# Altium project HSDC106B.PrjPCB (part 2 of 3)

## Sheet HSDC106B_EVM_DP83561_64p_PHY.SchDoc
size 431 x 279 mm; Date: Not shown in title block; ApprovedBy: Not shown in title block; CheckedBy: Not shown in title block; Author: Not shown in title block; CompanyName: Not shown in title block; DrawnBy: Justin Lazaruk; Engineer: Not shown in title block; Organization: Not shown in title block; Address1: Not shown in title block; Address2: Not shown in title block; Address3: Not shown in title block; Address4: Not shown in title block; DocumentNumber: 2; Revision: Use project parameter SCH_Rev; SheetNumber: 2; SheetTotal: 9; PageSetup: Record=PageOptions¦CenterHorizontal=True¦CenterVertical=True¦PrintScale=1.00¦XCorrection=1.00¦YCorrection=1.00¦PrintKind=0¦BorderSize=5000000¦LeftOffset=0¦BottomOffset=0¦Orientation=2¦PaperLength=1000¦PaperWidth=1000¦Scale=100¦PaperSource=15¦PrintQuality=600¦MediaType=1¦DitherType=10¦PaperKind=Letter¦PrintScaleMode=1
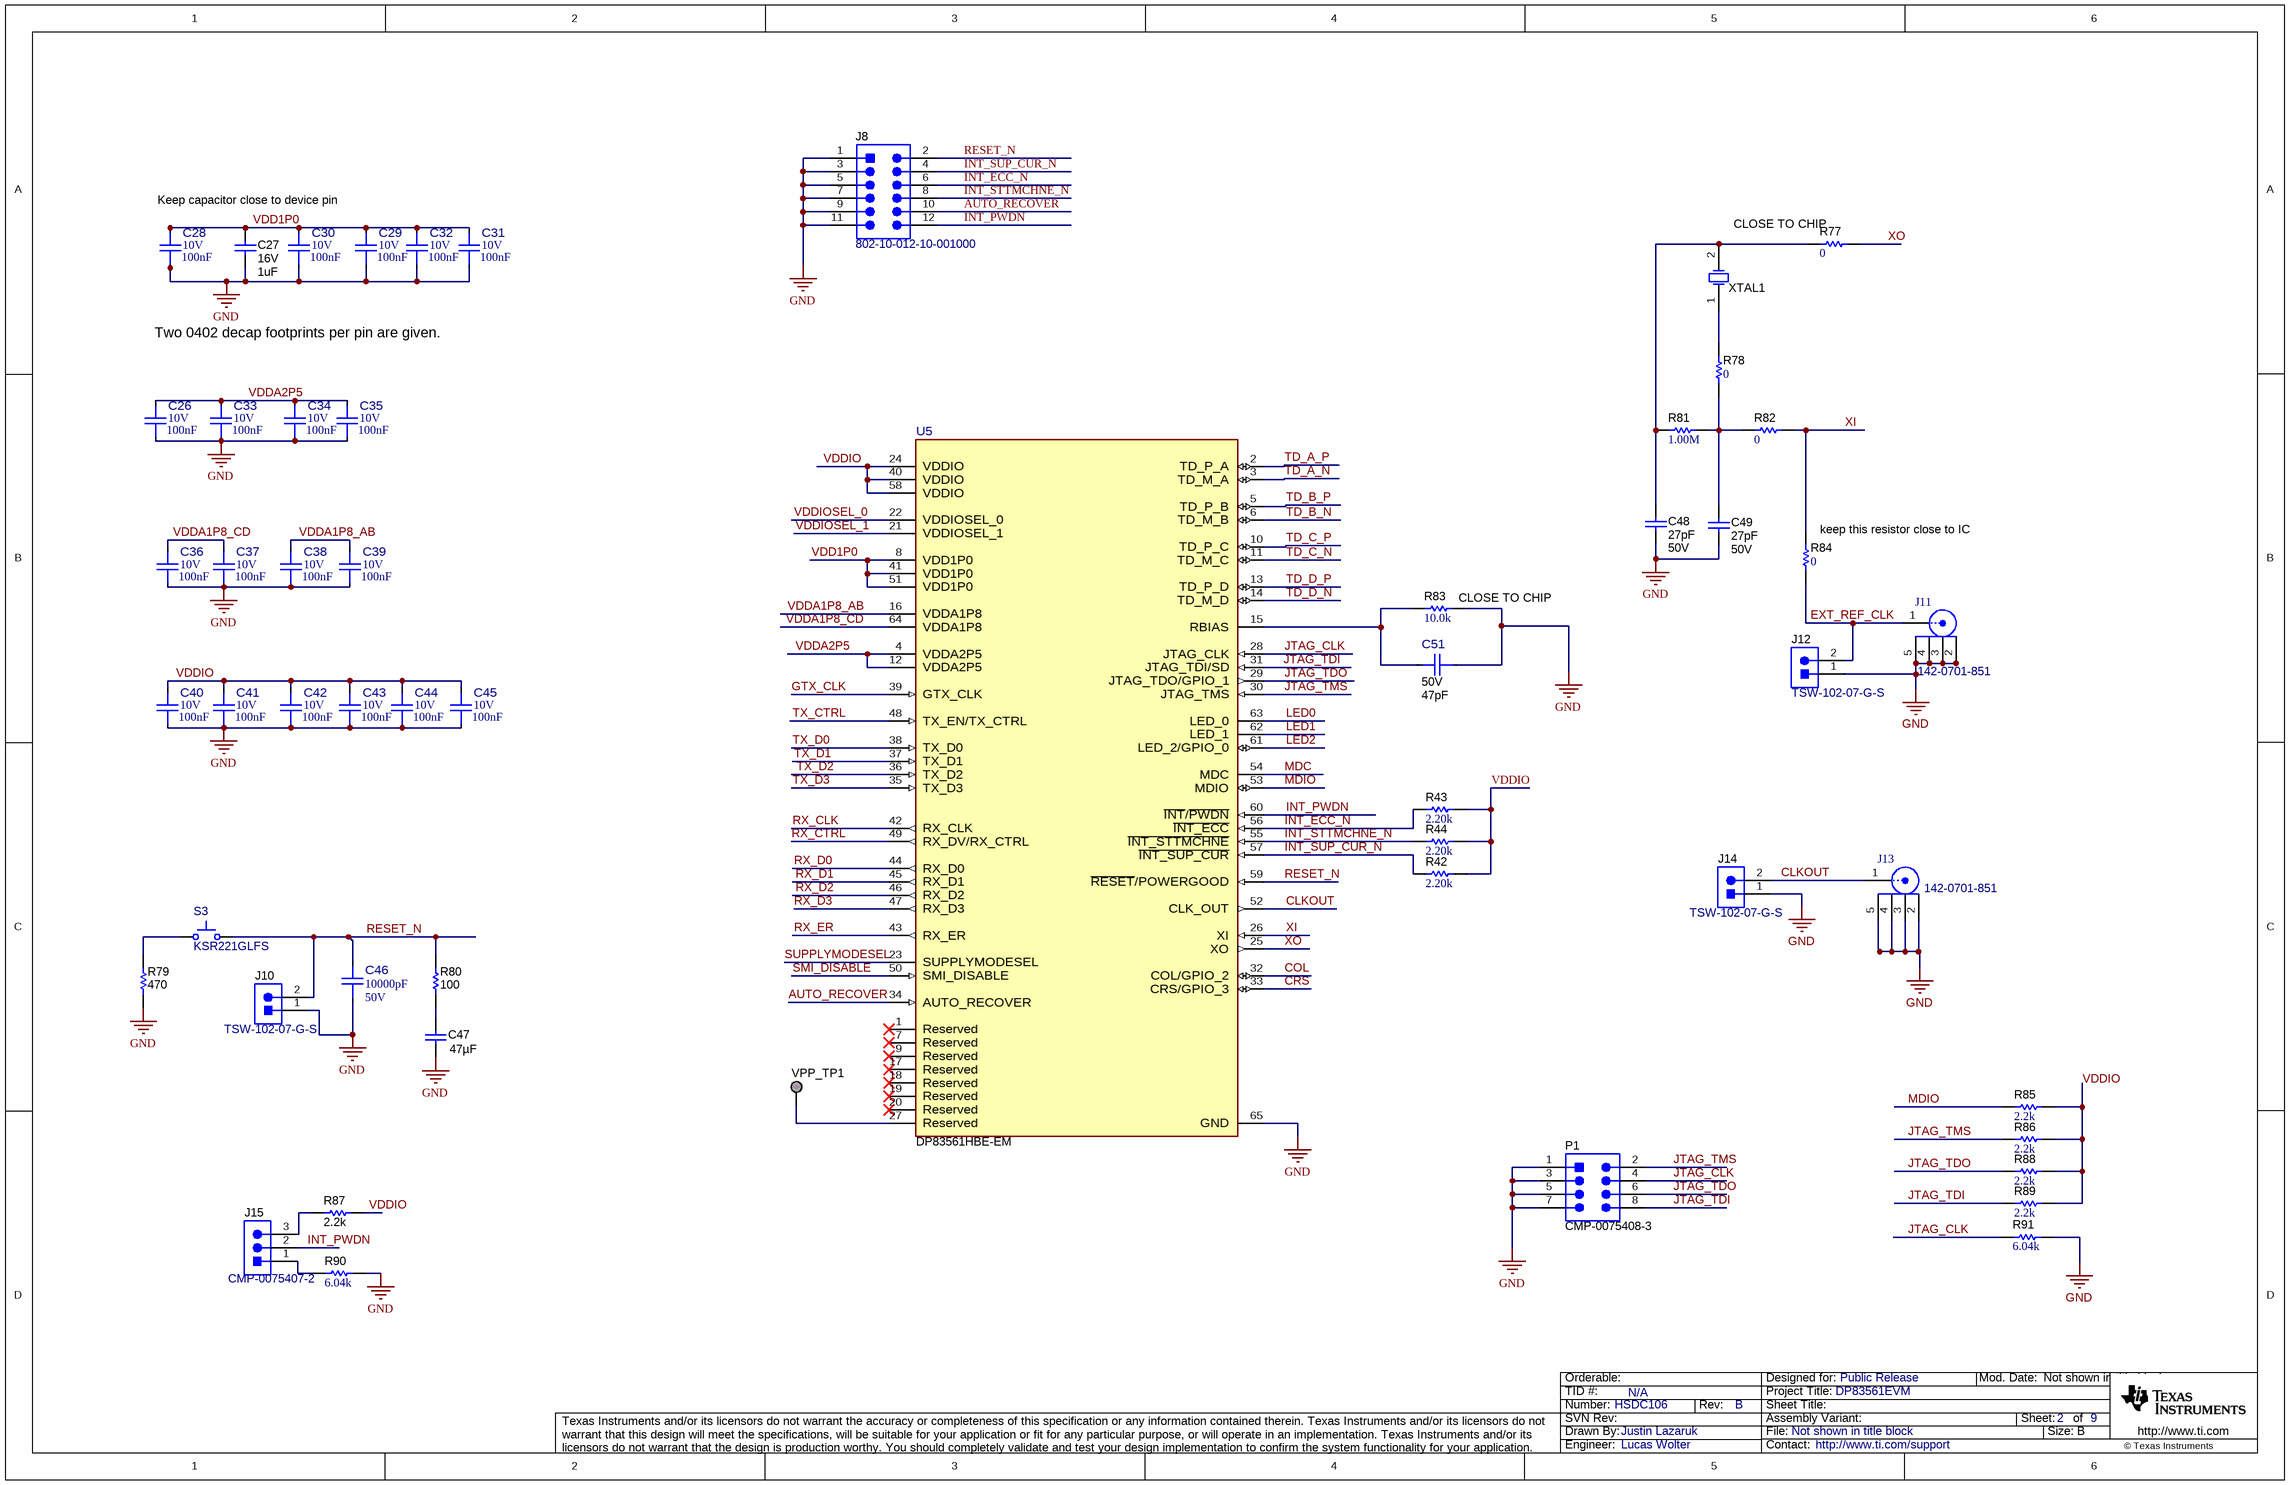
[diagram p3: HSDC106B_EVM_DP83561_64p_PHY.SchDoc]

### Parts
C26  VDC_V: 10V  ValueDisplayed: 100nF  [FP-CC0402KRX5R6BB104_0402-MFG]  (hidden comment: CC0402KRX5R6BB104)
C27  VDC_V: 16V  ValueDisplayed: 1uF  [0402]  (hidden comment: EMK105BJ105KVHF)
C28  VDC_V: 10V  ValueDisplayed: 100nF  [FP-CC0402KRX5R6BB104_0402-MFG]  (hidden comment: CC0402KRX5R6BB104)
C29  VDC_V: 10V  ValueDisplayed: 100nF  [FP-CC0402KRX5R6BB104_0402-MFG]  (hidden comment: CC0402KRX5R6BB104)
C30  VDC_V: 10V  ValueDisplayed: 100nF  [FP-CC0402KRX5R6BB104_0402-MFG]  (hidden comment: CC0402KRX5R6BB104)
C31  VDC_V: 10V  ValueDisplayed: 100nF  [FP-CC0402KRX5R6BB104_0402-MFG]  (hidden comment: CC0402KRX5R6BB104)
C32  VDC_V: 10V  ValueDisplayed: 100nF  [FP-CC0402KRX5R6BB104_0402-MFG]  (hidden comment: CC0402KRX5R6BB104)
C33  VDC_V: 10V  ValueDisplayed: 100nF  [FP-CC0402KRX5R6BB104_0402-MFG]  (hidden comment: CC0402KRX5R6BB104)
C34  VDC_V: 10V  ValueDisplayed: 100nF  [FP-CC0402KRX5R6BB104_0402-MFG]  (hidden comment: CC0402KRX5R6BB104)
C35  VDC_V: 10V  ValueDisplayed: 100nF  [FP-CC0402KRX5R6BB104_0402-MFG]  (hidden comment: CC0402KRX5R6BB104)
C36  VDC_V: 10V  ValueDisplayed: 100nF  [FP-CC0402KRX5R6BB104_0402-MFG]  (hidden comment: CC0402KRX5R6BB104)
C37  VDC_V: 10V  ValueDisplayed: 100nF  [FP-CC0402KRX5R6BB104_0402-MFG]  (hidden comment: CC0402KRX5R6BB104)
C38  VDC_V: 10V  ValueDisplayed: 100nF  [FP-CC0402KRX5R6BB104_0402-MFG]  (hidden comment: CC0402KRX5R6BB104)
C39  VDC_V: 10V  ValueDisplayed: 100nF  [FP-CC0402KRX5R6BB104_0402-MFG]  (hidden comment: CC0402KRX5R6BB104)
C40  VDC_V: 10V  ValueDisplayed: 100nF  [FP-CC0402KRX5R6BB104_0402-MFG]  (hidden comment: CC0402KRX5R6BB104)
C41  VDC_V: 10V  ValueDisplayed: 100nF  [FP-CC0402KRX5R6BB104_0402-MFG]  (hidden comment: CC0402KRX5R6BB104)
C42  VDC_V: 10V  ValueDisplayed: 100nF  [FP-CC0402KRX5R6BB104_0402-MFG]  (hidden comment: CC0402KRX5R6BB104)
C43  VDC_V: 10V  ValueDisplayed: 100nF  [FP-CC0402KRX5R6BB104_0402-MFG]  (hidden comment: CC0402KRX5R6BB104)
C44  VDC_V: 10V  ValueDisplayed: 100nF  [FP-CC0402KRX5R6BB104_0402-MFG]  (hidden comment: CC0402KRX5R6BB104)
C45  VDC_V: 10V  ValueDisplayed: 100nF  [FP-CC0402KRX5R6BB104_0402-MFG]  (hidden comment: CC0402KRX5R6BB104)
C46  ValueDisplayed: 10000pF  VDC_V: 50V  [FP-885012205067_0402-MFG]  (hidden comment: 885012205067)
C47  ValueDisplayed: 47µF  [0805_HV]  (hidden comment: GRM21BC80G476ME15L)
C48  ValueDisplayed: 27pF  VDC_V: 50V  [0603]  (hidden comment: CMP-0007116-4)
C49  ValueDisplayed: 27pF  VDC_V: 50V  [0603]  (hidden comment: CMP-0007116-4)
C51  VDC_V: 50V  ValueDisplayed: 47pF  [FP-GCM1555C1H470FA16D_0402-MFG]  (hidden comment: GCM1555C1H470FA16D)
J8  802-10-012-10-001000  [Mill-Max_802-10-012-10-001000]
J10  TSW-102-07-G-S  [TSW-102-07-G-S]
J11  142-0701-851  [Emerson_142-0701-851]
J12  TSW-102-07-G-S  [TSW-102-07-G-S]
J13  142-0701-851  [Emerson_142-0701-851]
J14  TSW-102-07-G-S  [TSW-102-07-G-S]
J15  CMP-0075407-2  [TSW-103-07-G-S]
P1  CMP-0075408-3  [TSW-104-07-G-D]
R42  ValueDisplayed: 2.20k  [0402]  (hidden comment: ERJ-2RKF2201X)
R43  ValueDisplayed: 2.20k  [0402]  (hidden comment: ERJ-2RKF2201X)
R44  ValueDisplayed: 2.20k  [0402]  (hidden comment: ERJ-2RKF2201X)
R77  ValueDisplayed: 0  [0603]  (hidden comment: CMP-0025885-5)
R78  ValueDisplayed: 0  [0603]  (hidden comment: CMP-0025885-5)
R79  ValueDisplayed: 470  [0402]  (hidden comment: CRCW0402470RJNED)
R80  ValueDisplayed: 100  [0402]  (hidden comment: ERJ-2GEJ101X)
R81  ValueDisplayed: 1.00M  [0402]  (hidden comment: CMP-0026727-1)
R82  ValueDisplayed: 0  [0603]  (hidden comment: CMP-0025885-5)
R83  ValueDisplayed: 10.0k  [0402]  (hidden comment: RMCF0402FT10K0)
R84  ValueDisplayed: 0  [0603]  (hidden comment: CMP-0025885-5)
R85  ValueDisplayed: 2.2k  [0402]  (hidden comment: CMP-0026890-5)
R86  ValueDisplayed: 2.2k  [0402]  (hidden comment: CMP-0026890-5)
R87  ValueDisplayed: 2.2k  [0402]  (hidden comment: CMP-0026890-5)
R88  ValueDisplayed: 2.2k  [0402]  (hidden comment: CMP-0026890-5)
R89  ValueDisplayed: 2.2k  [0402]  (hidden comment: CMP-0026890-5)
R90  ValueDisplayed: 6.04k  [0603]  (hidden comment: CMP-0023246-5)
R91  ValueDisplayed: 6.04k  [0603]  (hidden comment: CMP-0022558-4)
S3  KSR221GLFS  [KSR]
U5  PartNumber: DP83561HBE-EM  [HBE0064B-MFG]  (hidden comment: DP83561HBE/EM)
VPP_TP1  TP_H0.45P0.75  [TP_H045P075]  (value not drawn)  (no BOM)
XTAL1  ABM3-25.000MHZ-D2Y-T  [XTAL_ABM3]  (value not drawn)

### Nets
GND: C26.1 C27.2 C28.1 C29.1 C30.1 C31.1 C32.1 C33.1 C34.1 C35.1 C36.1 C37.1 C38.1 C39.1 C40.1 C41.1 C42.1 C43.1 C44.1 C45.1 C46.1 C47.2 C48.2 C49.2 C51.1 J8.1 J8.3 J8.5 J8.7 J8.9 J8.11 J10.1 J11.2 J11.3 J11.4 J11.5 J12.1 J13.2 J13.3 J13.4 J13.5 J14.1 P1.1 P1.3 P1.5 P1.7 R79.2 R83.2 R90.1 R91.1 U5.65(GND)
VDDIO: C40.2 C41.2 C42.2 C43.2 C44.2 C45.2 R42.2 R43.2 R44.2 R85.1 R86.1 R87.2 R88.1 R89.1 U5.24(VDDIO) U5.40(VDDIO) U5.58(VDDIO)
AUTO_RECOVER: J8.10 U5.34(AUTO_RECOVER)
CLKOUT: J13.1 J14.2 U5.52(CLK_OUT)
COL: U5.32(COL/GPIO_2)
CRS: U5.33(CRS/GPIO_3)
EXT_REF_CLK: J11.1 J12.2 R84.1
GTX_CLK: U5.39(GTX_CLK)
INT_ECC_N: J8.6 R43.1 U5.56(~{INT_ECC})
INT_PWDN: J8.12 J15.2 U5.60(~{INT}/~{PWDN})
INT_STTMCHNE_N: J8.8 R44.1 U5.55(~{INT_STTMCHNE})
INT_SUP_CUR_N: J8.4 R42.1 U5.57(~{INT_SUP_CUR})
JTAG_CLK: P1.4 R91.2 U5.28(JTAG_CLK)
JTAG_TDI: P1.8 R89.2 U5.31(JTAG_TDI/SD)
JTAG_TDO: P1.6 R88.2 U5.29(JTAG_TDO/GPIO_1)
JTAG_TMS: P1.2 R86.2 U5.30(JTAG_TMS)
LED0: U5.63(LED_0)
LED1: U5.62(LED_1)
LED2: U5.61(LED_2/GPIO_0)
MDC: U5.54(MDC)
MDIO: R85.2 U5.53(MDIO)
RESET_N: C46.2 J8.2 J10.2 R80.2 S3.2 U5.59(~{RESET}/POWERGOOD)
RX_CLK: U5.42(RX_CLK)
RX_CTRL: U5.49(RX_DV/RX_CTRL)
RX_D0: U5.44(RX_D0)
RX_D1: U5.45(RX_D1)
RX_D2: U5.46(RX_D2)
RX_D3: U5.47(RX_D3)
RX_ER: U5.43(RX_ER)
SMI_DISABLE: U5.50(SMI_DISABLE)
SUPPLYMODESEL: U5.23(SUPPLYMODESEL)
TD_A_N: U5.3(TD_M_A)
TD_A_P: U5.2(TD_P_A)
TD_B_N: U5.6(TD_M_B)
TD_B_P: U5.5(TD_P_B)
TD_C_N: U5.11(TD_M_C)
TD_C_P: U5.10(TD_P_C)
TD_D_N: U5.14(TD_M_D)
TD_D_P: U5.13(TD_P_D)
TX_CTRL: U5.48(TX_EN/TX_CTRL)
TX_D0: U5.38(TX_D0)
TX_D1: U5.37(TX_D1)
TX_D2: U5.36(TX_D2)
TX_D3: U5.35(TX_D3)
VDD1P0: C27.1 C28.2 C29.2 C30.2 C31.2 C32.2 U5.8(VDD1P0) U5.41(VDD1P0) U5.51(VDD1P0)
VDDA1P8_AB: C38.2 C39.2 U5.16(VDDA1P8)
VDDA1P8_CD: C36.2 C37.2 U5.64(VDDA1P8)
VDDA2P5: C26.2 C33.2 C34.2 C35.2 U5.4(VDDA2P5) U5.12(VDDA2P5)
VDDIOSEL_0: U5.22(VDDIOSEL_0)
VDDIOSEL_1: U5.21(VDDIOSEL_1)
XI: R82.2 R84.2 U5.26(XI)
XO: R77.2 U5.25(XO)
NetC47_1: C47.1 R80.1
NetC48_1: C48.1 R77.1 R81.1 XTAL1.2(OSC2)
NetC49_1: C49.1 R78.1 R81.2 R82.1
NetC51_2: C51.2 R83.1 U5.15(RBIAS)
NetJ15_1: J15.1 R90.2
NetJ15_3: J15.3 R87.1
NetR78_2: R78.2 XTAL1.1(OSC1)
NetR79_1: R79.1 S3.1
NetU5_27: U5.27(Reserved) VPP_TP1.1

Not connected (* = marked no-connect by the designer): U5 1(Reserved)* 7(Reserved)* 9(Reserved)* 17(Reserved)* 18(Reserved)* 19(Reserved)* 20(Reserved)*

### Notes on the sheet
- Keep capacitor close to device pin
- (near R77) CLOSE TO CHIP
- Two 0402 decap footprints per pin are given.
- (near R84) keep this resistor close to IC
- (near R83) CLOSE TO CHIP

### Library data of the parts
C26 C28-C45 = CMP-0093115-1: 0402 0.1 uF 10 V ±10 % Tolerance X5R SMT Multilayer Ceramic Capacitor; Manufacturer: YAGEO; SizeZ_mm: 0.55mm; AEC Qualified: No; AEC Grade: NA; Value: 100nF; TempCo: 30ppm/°C; Tolerance_%: 10%
C27 = CMP-0006347-2: CAP, CERM, 1 uF, 16 V, +/- 10%, X5R, 0402; Manufacturer: Taiyo Yuden; TaMin_C: -55°C; Polarized: N; SizeAreaWB_mm2: 3; Value1: Unknown; U/M: EA; Value: 1uF; TaMax_C: 85°C; SizeZ_mm: 0.6; SizeX_mm: 1; SizeY_mm: 0.5; Cap_F: 1µF; AEC Category: Q200
C46 = CMP-0090364-1: 10000pF ±10% 50V Ceramic Capacitor X7R 0402 (1005 Metric); Manufacturer: Wurth Electronics; Cap_F: 10nF; Value: 10nF; TempCo: 15%; SizeZ_mm: 0.55mm; AEC Qualified: No
C47 = CMP-0079541-1: CAP, CERM, 47 µF, 4 V,+/- 20%, X6S, 0805; Manufacturer: MuRata; SizeAreaWB_mm2: 6.75; SizeArea_mm2: 2.5; AEC Qualified: N; AEC Category: Q200; Value: 47uF; TaMax_C: 105°C; SizeZ_mm: 1.45; TaMin_C: -55°C; VDC_V: 4V; SizeY_mm: 1.25; U/M: EA; CompType: Capacitor; SizeX_mm: 2; Cap_Case: 0805
C48 C49 = CMP-0007116-4: CAP, CERM, 27 pF, 50 V, +/- 1%, C0G/NP0, 0603; PartNumber: CL10C270FB8NNNC; Manufacturer: Samsung Electro-Mechanics; Polarized: N; Value: 27pF; U/M: EA; Value1: Unknown; TaMin_C: -55°C; TaMax_C: 125°C; SizeAreaWB_mm2: 4.68; SizeZ_mm: 1; SizeX_mm: 1.6; SizeY_mm: 0.8; SizeArea_mm2: 1.28; AEC Category: Q200
C51 = CMP-0091135-2: Ceramic Capacitor for Automotive 47pF ±1% 50VDC C0G 0402 Paper T/R; Manufacturer: Murata; TempCo: 30ppm/°C; AEC Qualified: Yes; SizeZ_mm: 0.55mm; AEC Grade: Grade 1
J8 = CMP-0055098-2: Header, 2.54 mm, 6x2, Gold, TH; Manufacturer: Mill-Max; Shrouded: N; Gender: Male; Row_Count: 2; RowSpacing_mm: 2.54
J10 J12 J14 = CMP-0075405-3: Header, 100mil, 2x1, Gold, TH; Manufacturer: Samtec; Pitch_mm: 2.54; Gender: Male; Shrouded: N; Row_Count: 1; Current_A: 6.3A; Voltage_V: 550V; Cert_CSA: Y; Green_REACh: Passed; Green_Lifecycle: Active
J11 J13 = CMP-0055822-3: Connector, End launch SMA, 50 ohm, SMT; Manufacturer: Cinch Connectivity; Green_Lifecycle: Not Set; Green_REACh: Incomplete
J15 = CMP-0075407-2: Header, 100mil, 3x1, Gold, TH; Manufacturer: Samtec; Pitch_mm: 2.54; Gender: Male; Shrouded: N; Row_Count: 1; Current_A: 6.3A; Voltage_V: 550V; Cert_CSA: Y; Green_REACh: Passed; Green_Lifecycle: Active
P1 = CMP-0075408-3: Header, 100mil, 4x2, Gold, TH; Manufacturer: Samtec; Gender: Male; Row_Count: 2; Cert_CSA: Y; Pitch_mm: 2.54; Green_REACh: Passed; Voltage_V: 550V; Current_A: 6.3A; Green_Lifecycle: Active; Cert_CULUS: N
R42-R44 = CMP-0026681-1: RES, 2.20 k, 1%, 0.1 W, 0402; Manufacturer: Panasonic; Power_W: 100mW; TempCo: 100 ppm/C; Value_Code: 2k20; U/M: EA; Value: 2.20k; Res_ohm: 2.2k; SizeX_mm: 1; SizeY_mm: 0.5; SizeZ_mm: 0.6; Value2: 0.1W; VDC_V: 50V; AEC Category: Q200
R77 R78 R82 R84 = CMP-0025885-5: RES, 0, 5%, 0.1 W, 0603; PartNumber: RC0603JR-070RL; Manufacturer: Yageo; Value: 0; Value_Code: 0000; Power_W: 100mW; Value2: 0.1W; VDC_V: 75V; TempCo: 200 ppm/C; EIA_Code: E24; SizeX_mm: 1.6; SizeZ_mm: 1; SizeArea_mm2: 1.28; AEC Qualified: N; AEC Category: Q200; SizeY_mm: 0.8; SizeAreaWB_mm2: 4.68
R79 = CMP-0026934-3: RES, 470, 5%, 0.063 W, AEC-Q200 Grade 0, 0402; Manufacturer: Vishay-Dale; Value: 470; Value_Code: 470R; Power_W: 63mW; Value2: 0.063W; VDC_V: 50V; TempCo: 200 ppm/C; EIA_Code: E24; AEC Category: Q200; AEC Grade: 0; AEC Qualified: Y; SizeArea_mm2: 0.5; SizeX_mm: 1; SizeZ_mm: 0.6
R80 = CMP-0026993-2: RES, 100, 5%, 0.1 W, AEC-Q200 Grade 0, 0402; Manufacturer: Panasonic; Power_W: 100mW; TempCo: 200 ppm/C; Value_Code: 100R; U/M: EA; Value: 100; EIA_Code: E24; SizeX_mm: 1; SizeY_mm: 0.5; SizeZ_mm: 0.6; Value2: 0.1W; AEC Qualified: Y; AEC Grade: 0; AEC Category: Q200
R81 = CMP-0026727-1: RES, 1.00 M, 1%, 0.063 W, 0402; PartNumber: RC0402FR-071ML; Manufacturer: Yageo America; Value: 1.00Meg; Res_ohm: 1M; Value_Code: 1M00; Power_W: 63mW; Value2: 0.063W; TempCo: 100 ppm/C; EIA_Code: E96; U/M: EA; SizeX_mm: 1; SizeY_mm: 0.5; SizeZ_mm: 0.6; AEC Category: Q200
R83 = CMP-0026754-1: RES, 10.0 k, 1%, 0.063 W, AEC-Q200 Grade 0, 0402; Manufacturer: Stackpole Electronics Inc; Power_W: 63mW; TempCo: 100 ppm/C; Value_Code: 10k0; U/M: EA; Value: 10.0k; EIA_Code: E96; Res_ohm: 10k; SizeX_mm: 1; SizeY_mm: 0.5; SizeZ_mm: 0.6; Value2: 0.063W; AEC Qualified: Y; VDC_V: 50V; AEC Grade: 0; AEC Category: Q200
R85-R89 = CMP-0026890-5: RES, 2.2 k, 5%, 0.063 W, AEC-Q200 Grade 0, 0402; PartNumber: CRCW04022K20JNED; Manufacturer: Vishay-Dale; Value: 2.2k; Value_Code: 2k20; Power_W: 63mW; Value2: 0.063W; VDC_V: 50V; TempCo: 200 ppm/C; EIA_Code: E24; SizeX_mm: 1; SizeY_mm: 0.5; SizeZ_mm: 0.6; AEC Qualified: Y; AEC Category: Q200; AEC Grade: 0
R90 = CMP-0023246-5: RES, 6.04 k, 1%, 0.1 W, 0603; PartNumber: RC0603FR-076K04L; Manufacturer: Yageo; Value: 6.04k; Value_Code: 6k04; Power_W: 100mW; Value2: 0.1W; VDC_V: 75V; TempCo: 100 ppm/C; EIA_Code: E96; SizeX_mm: 1.6; SizeY_mm: 0.8; SizeZ_mm: 1; SizeArea_mm2: 1.28; AEC Qualified: N; AEC Category: Q200; SizeAreaWB_mm2: 4.68
R91 = CMP-0022558-4: RES, 6.04 k, 1%, 0.1 W, AEC-Q200 Grade 0, 0603; PartNumber: CRCW06036K04FKEA; Manufacturer: Vishay-Dale; Value: 6.04k; Value_Code: 6k04; Power_W: 100mW; Value2: 0.1W; VDC_V: 75V; TempCo: 100 ppm/C; EIA_Code: E96; SizeX_mm: 1.6; SizeY_mm: 0.8; SizeZ_mm: 1; SizeArea_mm2: 1.28; AEC Qualified: Y; AEC Category: Q200; AEC Grade: 0
S3 = CMP-0002170-2: Switch, Normally open, 2.3N force, 200k operations, SMD; Manufacturer: C&K Components; CurrentRating_mA: 1.001kA; SwitchFunction: Off-Mom; Circuit: SPST Switch; VDC_V: 32V; PositionCount: 1
U5 = CMP-0090870-2: Hi-Reliability, High Immunity, Radiation Resistant, Gigabit Ethernet PHY; Manufacturer: Texas Instruments; Data Rate: 1000Mbits/s; Simplex Duplex: Full-Duplex; Min Supply Voltage: 1.045V; Max Supply Voltage: 3.45V; Interface: Ethernet,Other; Number Of Channels: 1; SizeZ_mm: 3.53mm; AEC Qualified: No; AEC Category: Q200; CompType: IC
VPP_TP1 = CMP-0003719-1: Testpoint; Manufacturer: Texas Instruments; CompType: Pad
XTAL1 = CMP-0004620-3: Crystal, 25 MHz, 18 pF, SMD; Manufacturer: Abracon Corporation; TaMin_C: -40°C; Frequency Stability: +/-30ppm; Frequency_Fixed: 25MHz; TaMax_C: 85°C

## Sheet HSDC106B_EVM_DP83561_64p_MSP430.SchDoc
size 431 x 279 mm; Date: Not shown in title block; ApprovedBy: Not shown in title block; CheckedBy: Not shown in title block; Author: Not shown in title block; CompanyName: Not shown in title block; DrawnBy: Justin Lazaruk; Engineer: Not shown in title block; Organization: Not shown in title block; Address1: Not shown in title block; Address2: Not shown in title block; Address3: Not shown in title block; Address4: Not shown in title block; DocumentNumber: 7; Revision: Use project parameter SCH_Rev; SheetNumber: 7; SheetTotal: 9; PageSetup: Record=PageOptions¦CenterHorizontal=True¦CenterVertical=True¦PrintScale=1.00¦XCorrection=1.00¦YCorrection=1.00¦PrintKind=0¦BorderSize=5000000¦LeftOffset=0¦BottomOffset=0¦Orientation=2¦PaperLength=1000¦PaperWidth=1000¦Scale=100¦PaperSource=15¦PrintQuality=600¦MediaType=1¦DitherType=10¦PaperKind=Letter¦PrintScaleMode=1
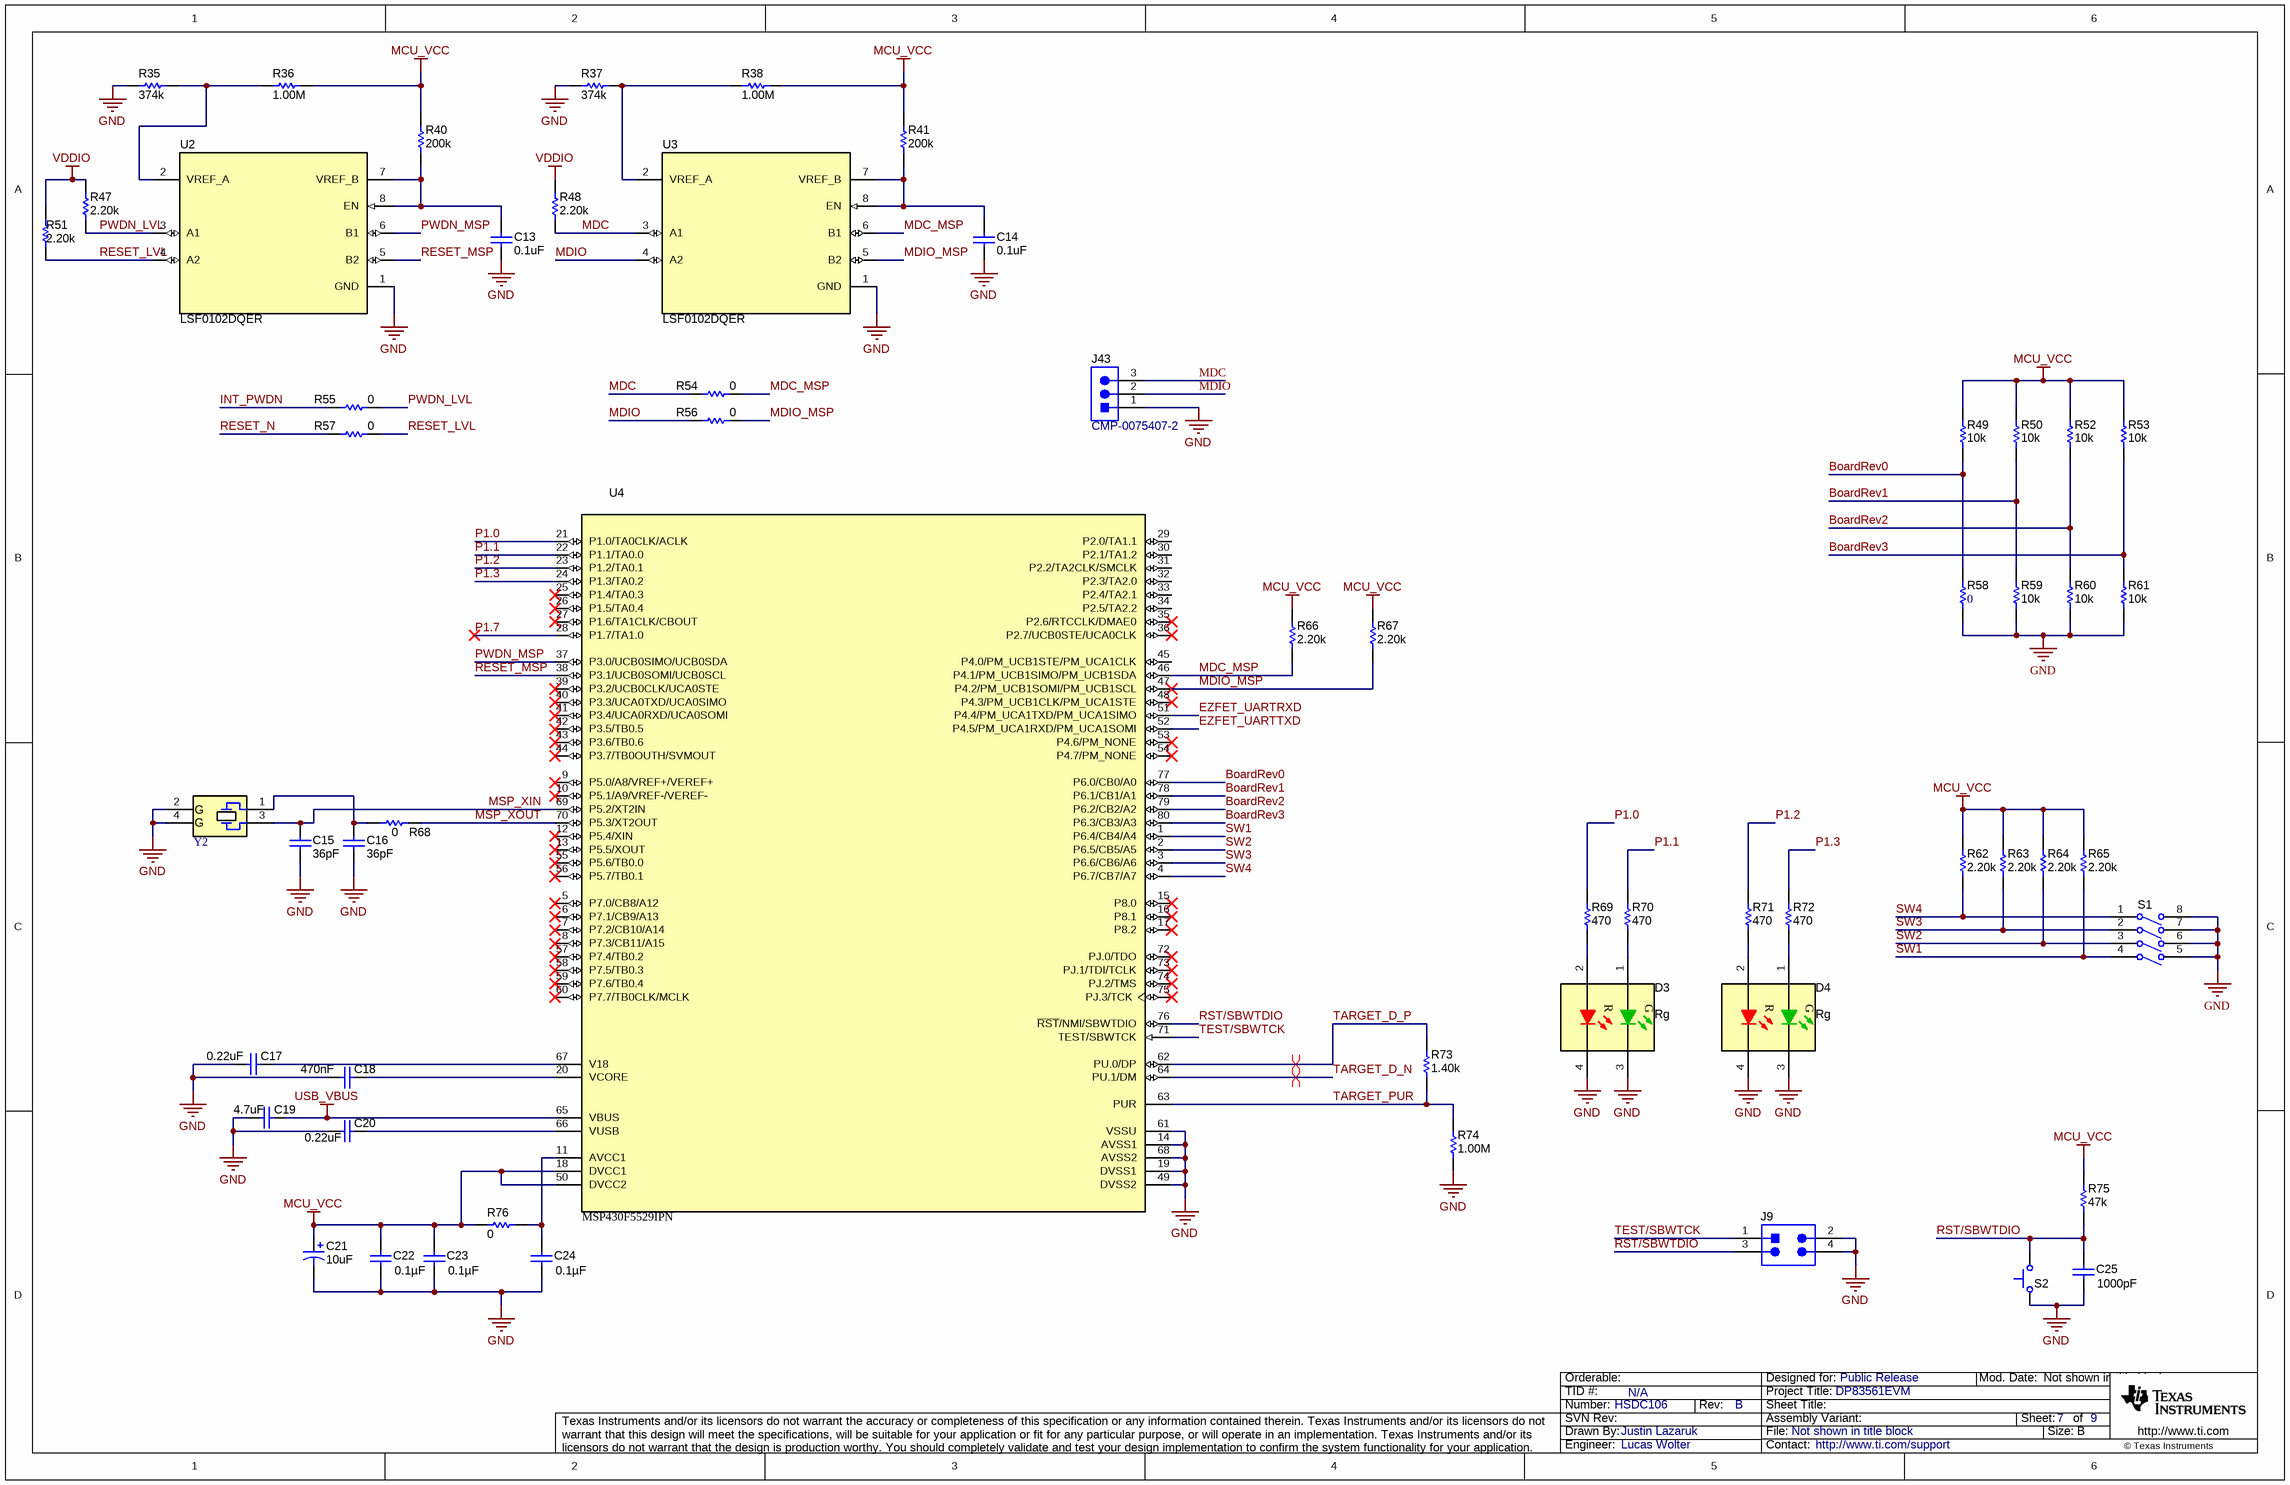
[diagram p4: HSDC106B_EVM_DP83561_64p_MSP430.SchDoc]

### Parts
C13  ValueDisplayed: 0.1uF  [0402]  (hidden comment: GCM155R71H104KE02D)
C14  ValueDisplayed: 0.1uF  [0402]  (hidden comment: GCM155R71H104KE02D)
C15  ValueDisplayed: 36pF  [0402]  (hidden comment: CL05C360JB5NNNC)
C16  ValueDisplayed: 36pF  [0402]  (hidden comment: CL05C360JB5NNNC)
C17  ValueDisplayed: 0.22uF  [0603]  (hidden comment: C0603C224Z4VACTU)
C18  Cap_F: 470nF  [0603]  (hidden comment: GCM188R71C474KA55D)
C19  ValueDisplayed: 4.7uF  [0603]  (hidden comment: C1608X5R1V475K080AC)
C20  ValueDisplayed: 0.22uF  [0603]  (hidden comment: C0603C224Z4VACTU)
C21  ValueDisplayed: 10uF  [7343-31]  (hidden comment: TPSD106K035R0125)
C22  ValueDisplayed: 0.1µF  [0402]  (hidden comment: C0402C104K8RACTU)
C23  ValueDisplayed: 0.1µF  [0402]  (hidden comment: C0402C104K8RACTU)
C24  ValueDisplayed: 0.1µF  [0402]  (hidden comment: C0402C104K8RACTU)
C25  ValueDisplayed: 1000pF  [0402]  (hidden comment: GRM1555C1H102JA01D)
D3  value Rg  [HSMF-C165_RG]  (hidden comment: HSMF-C165)
D4  value Rg  [HSMF-C165_RG]  (hidden comment: HSMF-C165)
J9  TSW-102-07-G-D  [TSW-102-07-G-D]  (value not drawn)
J43  CMP-0075407-2  [TSW-103-07-G-S]
R35  ValueDisplayed: 374k  [0402]  (hidden comment: CRCW0402374KFKED)
R36  ValueDisplayed: 1.00M  [0402]  (hidden comment: ERJ-2RKF1004X)
R37  ValueDisplayed: 374k  [0402]  (hidden comment: CRCW0402374KFKED)
R38  ValueDisplayed: 1.00M  [0402]  (hidden comment: ERJ-2RKF1004X)
R40  ValueDisplayed: 200k  [0603]  (hidden comment: CRCW0603200KJNEA)
R41  ValueDisplayed: 200k  [0603]  (hidden comment: CRCW0603200KJNEA)
R47  ValueDisplayed: 2.20k  [0402]  (hidden comment: CRCW04022K20FKED)
R48  ValueDisplayed: 2.20k  [0402]  (hidden comment: CRCW04022K20FKED)
R49  ValueDisplayed: 10k  [0402]  (hidden comment: CRCW040210K0JNED)
R50  ValueDisplayed: 10k  [0402]  (hidden comment: CRCW040210K0JNED)
R51  ValueDisplayed: 2.20k  [0402]  (hidden comment: CRCW04022K20FKED)
R52  ValueDisplayed: 10k  [0402]  (hidden comment: CRCW040210K0JNED)
R53  ValueDisplayed: 10k  [0402]  (hidden comment: CRCW040210K0JNED)
R54  ValueDisplayed: 0  [0402]  (hidden comment: ERJ-2GE0R00X)
R55  ValueDisplayed: 0  [0402]  (hidden comment: ERJ-2GE0R00X)
R56  ValueDisplayed: 0  [0402]  (hidden comment: ERJ-2GE0R00X)
R57  ValueDisplayed: 0  [0402]  (hidden comment: ERJ-2GE0R00X)
R58  ValueDisplayed: 0  [0402]  (hidden comment: ERJ-2GE0R00X)
R59  ValueDisplayed: 10k  [0402]  (hidden comment: CRCW040210K0JNED)
R60  ValueDisplayed: 10k  [0402]  (hidden comment: CRCW040210K0JNED)
R61  ValueDisplayed: 10k  [0402]  (hidden comment: CRCW040210K0JNED)
R62  ValueDisplayed: 2.20k  [0402]  (hidden comment: CRCW04022K20FKED)
R63  ValueDisplayed: 2.20k  [0402]  (hidden comment: CRCW04022K20FKED)
R64  ValueDisplayed: 2.20k  [0402]  (hidden comment: CRCW04022K20FKED)
R65  ValueDisplayed: 2.20k  [0402]  (hidden comment: CRCW04022K20FKED)
R66  ValueDisplayed: 2.20k  [0402]  (hidden comment: CRCW04022K20FKED)
R67  ValueDisplayed: 2.20k  [0402]  (hidden comment: CRCW04022K20FKED)
R68  ValueDisplayed: 0  [0402]  (hidden comment: CRCW04020000Z0ED)
R69  ValueDisplayed: 470  [0201]  (hidden comment: RC0201JR-07470RL)
R70  ValueDisplayed: 470  [0201]  (hidden comment: RC0201JR-07470RL)
R71  ValueDisplayed: 470  [0201]  (hidden comment: RC0201JR-07470RL)
R72  ValueDisplayed: 470  [0201]  (hidden comment: RC0201JR-07470RL)
R73  ValueDisplayed: 1.40k  [0402]  (hidden comment: CRCW04021K40FKED)
R74  ValueDisplayed: 1.00M  [0402]  (hidden comment: CRCW04021M00FKED)
R75  ValueDisplayed: 47k  [0402]  (hidden comment: CRCW040247K0JNED)
R76  ValueDisplayed: 0  [0402]  (hidden comment: CRCW04020000Z0ED)
S1  218-4LPST  [SW_218-4LPST]  (value not drawn)
S2  KSR221GLFS  [KSR]  (value not drawn)
U2  LSF0102DQER  [DQE0008A]
U3  LSF0102DQER  [DQE0008A]
U4  MSP430F5529IPN  [PN0080A_N]
Y2  ECS-240-20-33-DU-TR  [ECS_ECX-32]  (value not drawn)

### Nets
GND: C13.2 C14.2 C15.2 C16.2 C17.2 C18.2 C19.1 C20.2 C21.2(-) C22.2 C23.2 C24.2 C25.2 D3.3(K) D3.4(K) D4.3(K) D4.4(K) J9.2 J9.4 J43.1 R35.1 R37.1 R58.1 R59.1 R60.1 R61.1 R74.2 S1.5(B4) S1.6(B3) S1.7(B2) S1.8(B1) S2.1 U2.1(GND) U3.1(GND) U4.14(AVSS1) U4.19(DVSS1) U4.49(DVSS2) U4.61(VSSU) U4.68(AVSS2) Y2.2(GND) Y2.4(GND)
MCU_VCC: C21.1(+) C22.1 C23.1 R36.2 R38.2 R40.2 R41.2 R49.2 R50.2 R52.2 R53.2 R62.2 R63.2 R64.2 R65.2 R66.2 R67.2 R75.1 R76.1 U4.18(DVCC1) U4.50(DVCC2)
USB_VBUS: C19.2 U4.65(VBUS)
VDDIO: R47.2 R48.2 R51.2
BoardRev0: R49.1 R58.2 U4.77(P6.0/CB0/A0)
BoardRev1: R50.1 R59.2 U4.78(P6.1/CB1/A1)
BoardRev2: R52.1 R60.2 U4.79(P6.2/CB2/A2)
BoardRev3: R53.1 R61.2 U4.80(P6.3/CB3/A3)
EZFET_UARTRXD: U4.51(P4.4/PM_UCA1TXD/PM_UCA1SIMO)
EZFET_UARTTXD: U4.52(P4.5/PM_UCA1RXD/PM_UCA1SOMI)
INT_PWDN: R55.1
MDC: J43.3 R48.1 R54.1 U3.3(A1)
MDC_MSP: R54.2 R66.1 U3.6(B1) U4.46(P4.1/PM_UCB1SIMO/PM_UCB1SDA)
MDIO: J43.2 R56.1 U3.4(A2)
MDIO_MSP: R56.2 R67.1 U3.5(B2) U4.47(P4.2/PM_UCB1SOMI/PM_UCB1SCL)
MSP_XIN: C15.1 U4.69(P5.2/XT2IN) Y2.3
MSP_XOUT: R68.2 U4.70(P5.3/XT2OUT)
P1.0: R69.2 U4.21(P1.0/TA0CLK/ACLK)
P1.1: R70.2 U4.22(P1.1/TA0.0)
P1.2: R71.2 U4.23(P1.2/TA0.1)
P1.3: R72.2 U4.24(P1.3/TA0.2)
P1.7: U4.28(P1.7/TA1.0)
PWDN_LVL: R47.1 R55.2 U2.3(A1)
PWDN_MSP: U2.6(B1) U4.37(P3.0/UCB0SIMO/UCB0SDA)
RESET_LVL: R51.1 R57.2 U2.4(A2)
RESET_MSP: U2.5(B2) U4.38(P3.1/UCB0SOMI/UCB0SCL)
RESET_N: R57.1
RST/SBWTDIO: C25.1 J9.3 R75.2 S2.2 U4.76(~{RST}/NMI/SBWTDIO)
SW1: R65.1 S1.4(A4) U4.1(P6.4/CB4/A4)
SW2: R64.1 S1.3(A3) U4.2(P6.5/CB5/A5)
SW3: R63.1 S1.2(A2) U4.3(P6.6/CB6/A6)
SW4: R62.1 S1.1(A1) U4.4(P6.7/CB7/A7)
TARGET_D_N: U4.64(PU.1/DM)
TARGET_D_P: R73.2 U4.62(PU.0/DP)
TARGET_PUR: R73.1 R74.1 U4.63(PUR)
TEST/SBWTCK: J9.1 U4.71(TEST/SBWTCK)
NetC13_1: C13.1 R40.1 U2.7(VREF_B) U2.8(EN)
NetC14_1: C14.1 R41.1 U3.7(VREF_B) U3.8(EN)
NetC16_1: C16.1 R68.1 Y2.1
NetC17_1: C17.1 U4.67(V18)
NetC18_1: C18.1 U4.20(VCORE)
NetC20_1: C20.1 U4.66(VUSB)
NetC24_1: C24.1 R76.2 U4.11(AVCC1)
NetD3_1: D3.1(A) R70.1
NetD3_2: D3.2(A) R69.1
NetD4_1: D4.1(A) R72.1
NetD4_2: D4.2(A) R71.1
NetR35_2: R35.2 R36.1 U2.2(VREF_A)
NetR37_2: R37.2 R38.1 U3.2(VREF_A)

Not connected (* = marked no-connect by the designer): U4 5(P7.0/CB8/A12)* 6(P7.1/CB9/A13)* 7(P7.2/CB10/A14)* 8(P7.3/CB11/A15)* 9(P5.0/A8/VREF+/VEREF+)* 10(P5.1/A9/VREF-/VEREF-)* 12(P5.4/XIN)* 13(P5.5/XOUT)* 15(P8.0)* 16(P8.1)* 17(P8.2)* 25(P1.4/TA0.3)* 26(P1.5/TA0.4)* 27(P1.6/TA1CLK/CBOUT)* 29(P2.0/TA1.1) 30(P2.1/TA1.2) 31(P2.2/TA2CLK/SMCLK) 32(P2.3/TA2.0) 33(P2.4/TA2.1) 34(P2.5/TA2.2) 35(P2.6/RTCCLK/DMAE0)* 36(P2.7/UCB0STE/UCA0CLK)* 39(P3.2/UCB0CLK/UCA0STE)* 40(P3.3/UCA0TXD/UCA0SIMO)* 41(P3.4/UCA0RXD/UCA0SOMI)* 42(P3.5/TB0.5)* 43(P3.6/TB0.6)* 44(P3.7/TB0OUTH/SVMOUT)* 45(P4.0/PM_UCB1STE/PM_UCA1CLK) 48(P4.3/PM_UCB1CLK/PM_UCA1STE)* 53(P4.6/PM_NONE)* 54(P4.7/PM_NONE)* 55(P5.6/TB0.0)* 56(P5.7/TB0.1)* 57(P7.4/TB0.2)* 58(P7.5/TB0.3)* 59(P7.6/TB0.4)* 60(P7.7/TB0CLK/MCLK)* 72(PJ.0/TDO)* 73(PJ.1/TDI/TCLK)* 74(PJ.2/TMS)* 75(PJ.3/TCK)*

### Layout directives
differential pair: TARGET_D_N, TARGET_D_P

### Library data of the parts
C13 C14 = CMP-0006356-2: CAP, CERM, 0.1 uF, 50 V, +/- 10%, X7R, AEC-Q200 Grade 1, 0402; Manufacturer: MuRata; TaMin_C: -55°C; Polarized: N; SizeAreaWB_mm2: 3; Value1: Unknown; U/M: EA; Value: 0.1uF; TaMax_C: 125°C; SizeZ_mm: 0.6; SizeX_mm: 1; SizeY_mm: 0.5; Value2: 50V; AEC Qualified: Y; Cap_F: 100nF; AEC Category: Q200
C15 C16 = CMP-0083839-1: CAP, CERM, 36 pF, 50 V,+/- 5%, C0G/NP0, 0402; Manufacturer: Samsung Electro-Mechanics; SizeAreaWB_mm2: 3; SizeArea_mm2: 0.5; AEC Qualified: N; AEC Category: Q200; Value: 36pF; TaMax_C: 125°C; SizeZ_mm: 0.6; TaMin_C: -55°C; VDC_V: 50V; U/M: EA; SizeX_mm: 1
C17 C20 = CMP-0006905-4: CAP, CERM, 0.22 uF, 16 V, +80/-20%, Y5V, 0603; Manufacturer: Kemet; TaMin_C: -30°C; Polarized: N; SizeAreaWB_mm2: 4.68; Value1: Unknown; U/M: EA; Value: 0.22uF; TaMax_C: 85°C; Tolerance_%: 80%; SizeZ_mm: 1; SizeX_mm: 1.6; SizeY_mm: 0.8; Value2: 16V; SizeArea_mm2: 1.28; Cap_F: 220nF; AEC Category: Q200
C18 = CMP-0007138-4: CAP, CERM, 0.47 uF, 16 V, +/- 10%, X7R, AEC-Q200 Grade 1, 0603; Manufacturer: MuRata; TaMin_C: -55°C; Polarized: N; SizeAreaWB_mm2: 4.68; Value1: Unknown; U/M: EA; Value: 0.47uF; TaMax_C: 125°C; SizeZ_mm: 1; SizeX_mm: 1.6; SizeY_mm: 0.8; Value2: 16V; SizeArea_mm2: 1.28; AEC Qualified: Y; AEC Category: Q200
C19 = CMP-0007022-5: CAP, CERM, 4.7 uF, 35 V, +/- 10%, X5R, 0603; Manufacturer: TDK; Polarized: N; CompType: Capacitor; Value: 4.7uF; U/M: EA; Cap_F: 4.7µF; ESR_ohm: 3.728m; Value1: 0.003728 ohm; VDC_V: 35V; IRMS_A: 2.69359A; TaMin_C: -55°C; TaMax_C: 85°C; SizeArea_mm2: 1.28; SizeAreaWB_mm2: 4.68; SizeX_mm: 1.6; SizeY_mm: 0.8; SizeZ_mm: 1; AEC Category: Q200
C21 = CMP-0011855-2: CAP, TA, 10 uF, 35 V, +/- 10%, 0.125 ohm, SMD; Manufacturer: AVX; Polarized: Y; CompType: Capacitor; Value: 10uF; U/M: EA; Cap_F: 10µF; VDC_V: 35V; ESR_ohm: 1.25d; IRMS_A: 9.86dA; TaMin_C: -55°C; TaMax_C: 125°C; Cap_Case: D; AEC Category: Q200; SizeArea_mm2: 31.39; SizeAreaWB_mm2: 58.59; SizeX_mm: 7.3; SizeY_mm: 4.3; SizeZ_mm: 3.1
C22-C24 = CMP-0078241-1: CAP, CERM, 0.1 µF, 10 V,+/- 10%, X7R, 0402; Manufacturer: Kemet; TaMin_C: -55°C; Polarized: N; SizeAreaWB_mm2: 3; U/M: EA; Value: 0.1uF; TaMax_C: 125°C; SizeZ_mm: 0.6; SizeX_mm: 1; SizeY_mm: 0.5; Value2: 10V; Cap_F: 100nF; AEC Category: Q200
C25 = CMP-0006412-2: CAP, CERM, 1000 pF, 50 V, +/- 5%, C0G/NP0, 0402; Manufacturer: MuRata; TaMin_C: -55°C; Polarized: N; SizeAreaWB_mm2: 3; Value1: Unknown; U/M: EA; Value: 1000pF; TaMax_C: 125°C; SizeZ_mm: 0.6; SizeX_mm: 1; SizeY_mm: 0.5; Value2: 50V; Cap_F: 1nF; AEC Category: Q200
D3 D4 = CMP-0002934-2: LED, Rg, SMD; Manufacturer: Avago; Vf_V: 2.2V; Io_A: 20mA; Vr_V: 5V; Ir_A: 100µA; Tjmax_C: 85°C; Value1: W; LuminousIntensity_IV: 20; Angle: 120; U/M: EA
J9 = CMP-0075404-1: Header, 100mil, 2x2, Gold, TH; Manufacturer: Samtec; Pitch_mm: 2.54; Gender: Male; Shrouded: N; Row_Count: 2; Current_A: 6.3A; Voltage_V: 550V; Cert_CSA: Y; CNHeader: True; CT: False; Green_Lifecycle: Active; Green_REACh: Passed
J43 = CMP-0075407-2: as J15 on sheet HSDC106B_EVM_DP83561_64p_PHY
R35 R37 = CMP-0026317-2: RES, 374 k, 1%, 0.063 W, AEC-Q200 Grade 0, 0402; Manufacturer: Vishay-Dale; Power_W: 63mW; TempCo: 100 ppm/C; Value: 374k; EIA_Code: E96; SizeX_mm: 1; SizeY_mm: 0.5; SizeZ_mm: 0.6; Value2: 0.063W; AEC Qualified: Y; VDC_V: 50V; AEC Category: Q200; AEC Grade: 0
R36 R38 = CMP-0026660-1: RES, 1.00 M, 1%, 0.1 W, 0402; Manufacturer: Panasonic; Power_W: 100mW; TempCo: 100 ppm/C; Value_Code: 1M00; U/M: EA; Value: 1.00Meg; EIA_Code: E96; Res_ohm: 1M; SizeX_mm: 1; SizeY_mm: 0.5; SizeZ_mm: 0.6; Value2: 0.1W; VDC_V: 50V; AEC Category: Q200
R40 R41 = CMP-0025750-4: RES, 200 k, 5%, 0.1 W, AEC-Q200 Grade 0, 0603; Manufacturer: Vishay-Dale; Power_W: 100mW; TempCo: 200 ppm/C; Value: 200k; EIA_Code: E24; SizeX_mm: 1.6; SizeY_mm: 0.8; SizeZ_mm: 1; Value2: 0.1W; SizeArea_mm2: 1.28; AEC Qualified: Y; VDC_V: 75V; AEC Category: Q200; AEC Grade: 0
R47 R48 R51 R62-R67 = CMP-0026231-2: RES, 2.20 k, 1%, 0.063 W, AEC-Q200 Grade 0, 0402; Manufacturer: Vishay-Dale; Power_W: 63mW; TempCo: 100 ppm/C; Value_Code: 2k20; Value: 2.20k; Res_ohm: 2.2k; SizeX_mm: 1; SizeY_mm: 0.5; SizeZ_mm: 0.6; Value2: 0.063W; AEC Qualified: Y; AEC Category: Q200; AEC Grade: 0
R49 R50 R52 R53 R59-R61 = CMP-0026825-5: RES, 10 k, 5%, 0.063 W, AEC-Q200 Grade 0, 0402; Manufacturer: Vishay-Dale; Power_W: 63mW; TempCo: 200 ppm/C; Value_Code: 10k0; Value: 10k; EIA_Code: E24; SizeX_mm: 1; SizeY_mm: 0.5; SizeZ_mm: 0.6; Value2: 0.063W; AEC Qualified: Y; VDC_V: 50V; AEC Category: Q200; AEC Grade: 0
R54-R57 = CMP-0026992-3: RES, 0, 5%, 0.1 W, AEC-Q200 Grade 0, 0402; Manufacturer: Panasonic; Power_W: 100mW; TempCo: 600 ppm/C; Value_Code: 0000; Value: 0; EIA_Code: E24; SizeX_mm: 1; SizeY_mm: 0.5; SizeZ_mm: 0.6; Value2: 0.1W; AEC Qualified: Y; VDC_V: 50V; AEC Category: Q200; SizeAreaWB_mm2: 3
R58 = CMP-0026992-3: RES, 0, 5%, 0.1 W, AEC-Q200 Grade 0, 0402; Manufacturer: Panasonic; Value: 0; Value_Code: 0000; Power_W: 100mW; Value2: 0.1W; VDC_V: 50V; TempCo: 600 ppm/C; EIA_Code: E24; AEC Category: Q200; AEC Qualified: Y; SizeArea_mm2: 0.5; SizeX_mm: 1; SizeZ_mm: 0.6; SizeAreaWB_mm2: 3
R68 R76 = CMP-0026822-3: RES, 0, 5%, 0.063 W, AEC-Q200 Grade 0, 0402; Manufacturer: Vishay-Dale; Value: 0; Value_Code: 0000; Power_W: 63mW; Value2: 0.063W; VDC_V: 50V; TempCo: 200 ppm/C; EIA_Code: E24; AEC Category: Q200; AEC Qualified: Y; SizeArea_mm2: 0.5; SizeX_mm: 1; SizeZ_mm: 0.6
R69-R72 = CMP-0027127-1: RES, 470, 5%, 0.05 W, 0201; Manufacturer: Yageo America; Power_W: 50mW; TempCo: 200 ppm/C; Value_Code: 470R; U/M: EA; Value: 470; EIA_Code: E24; SizeX_mm: 0.6; SizeY_mm: 0.3; SizeZ_mm: 0.26; Value2: 0.05W; SizeArea_mm2: 0.18; AEC Qualified: N; VDC_V: 25V; AEC Category: Q200
R73 = CMP-0026085-3: RES, 1.40 k, 1%, 0.063 W, AEC-Q200 Grade 0, 0402; Manufacturer: Vishay-Dale; Value: 1.40k; Res_ohm: 1.4k; Value_Code: 1k40; Power_W: 63mW; Value2: 0.063W; VDC_V: 50V; TempCo: 100 ppm/C; EIA_Code: E96; AEC Category: Q200; AEC Qualified: Y; AEC Grade: 0; SizeArea_mm2: 0.5; SizeX_mm: 1; SizeZ_mm: 0.6
R74 = CMP-0026100-2: RES, 1.00 M, 1%, 0.063 W, AEC-Q200 Grade 0, 0402; Manufacturer: Vishay-Dale; Value: 1.00Meg; Res_ohm: 1M; Value_Code: 1M00; Power_W: 63mW; Value2: 0.063W; VDC_V: 50V; TempCo: 100 ppm/C; EIA_Code: E96; AEC Category: Q200; AEC Qualified: Y; AEC Grade: 0; SizeArea_mm2: 0.5; SizeX_mm: 1; SizeZ_mm: 0.6
R75 = CMP-0026935-3: RES, 47 k, 5%, 0.063 W, AEC-Q200 Grade 0, 0402; Manufacturer: Vishay-Dale; Value: 47k; Value_Code: 47k0; Power_W: 63mW; Value2: 0.063W; VDC_V: 50V; TempCo: 200 ppm/C; EIA_Code: E24; AEC Category: Q200; AEC Qualified: Y; AEC Grade: 0; SizeArea_mm2: 0.5; SizeX_mm: 1; SizeZ_mm: 0.6
S1 = CMP-0002128-2: Switch, Slide, SPST 4 poles, SMT; Manufacturer: CTS Electrocomponents; CurrentRating_mA: 25A; PositionCount: 4; VDC_V: 24V; SwitchFunction: Off-On
S2 = CMP-0002170-2: Switch, Normally open, 2.3N force, 200k operations, SMD; Manufacturer: C&K Components; Circuit: SPST Switch; VDC_V: 32V; SwitchFunction: Off-Mom; PositionCount: 1; CurrentRating_mA: 1.001kA
U2 U3 = CMP-0066434-1: Dual Bidirectional Multi-Voltage Level Translator, DQE0008A (X2SON-8); Alternate Manufacturer: Texas Instruments; SizeAreaWB_mm2: 4.8; U/M: EA; SizeZ_mm: 0.4; SizeX_mm: 1.0; SizeY_mm: 1.4; CompType: IC
U4 = CMP-0038965-1: 25 MHz Mixed Signal Microcontroller with 128 KB Flash, 8192 B SRAM and 63 GPIOs, -40 to 85 degC, 80-pin QFP (PN), Green (RoHS & no Sb/Br); Manufacturer: Texas Instruments; ADC: 12-bit SAR; ADC Channels: 16; Brown Out Reset: Yes; DMA: 3; Flash(KB): 128; Frequency(MHz): 25; GPIO: 63; Multiplier: 32x32; SRAM(B): 8192; SubFamily: 5 Series; Timers - 16-bit: 4; USB: 1; USCI_A (UART/LIN/IrDA/SPI): 2
Y2 = CMP-0004637-3: Crystal, 24 MHz, 20pF, SMD; Manufacturer: ECS Inc.; TaMin_C: -55°C; Frequency Stability: +/-100ppm; Frequency_Fixed: 24MHz; TaMax_C: 125°C

## Sheet HSDC106B_EVM_DP83561_64p_MAC_RJ45.SchDoc
size 431 x 279 mm; Date: Not shown in title block; ApprovedBy: Not shown in title block; CheckedBy: Not shown in title block; Author: Not shown in title block; CompanyName: Not shown in title block; DrawnBy: Justin Lazaruk; Engineer: Not shown in title block; Organization: Not shown in title block; Address1: Not shown in title block; Address2: Not shown in title block; Address3: Not shown in title block; Address4: Not shown in title block; DocumentNumber: 4; Revision: Use project parameter SCH_Rev; SheetNumber: 4; SheetTotal: 9; PageSetup: Record=PageOptions¦CenterHorizontal=True¦CenterVertical=True¦PrintScale=1.00¦XCorrection=1.00¦YCorrection=1.00¦PrintKind=0¦BorderSize=5000000¦LeftOffset=0¦BottomOffset=0¦Orientation=2¦PaperLength=1000¦PaperWidth=1000¦Scale=100¦PaperSource=15¦PrintQuality=600¦MediaType=1¦DitherType=10¦PaperKind=Letter¦PrintScaleMode=1
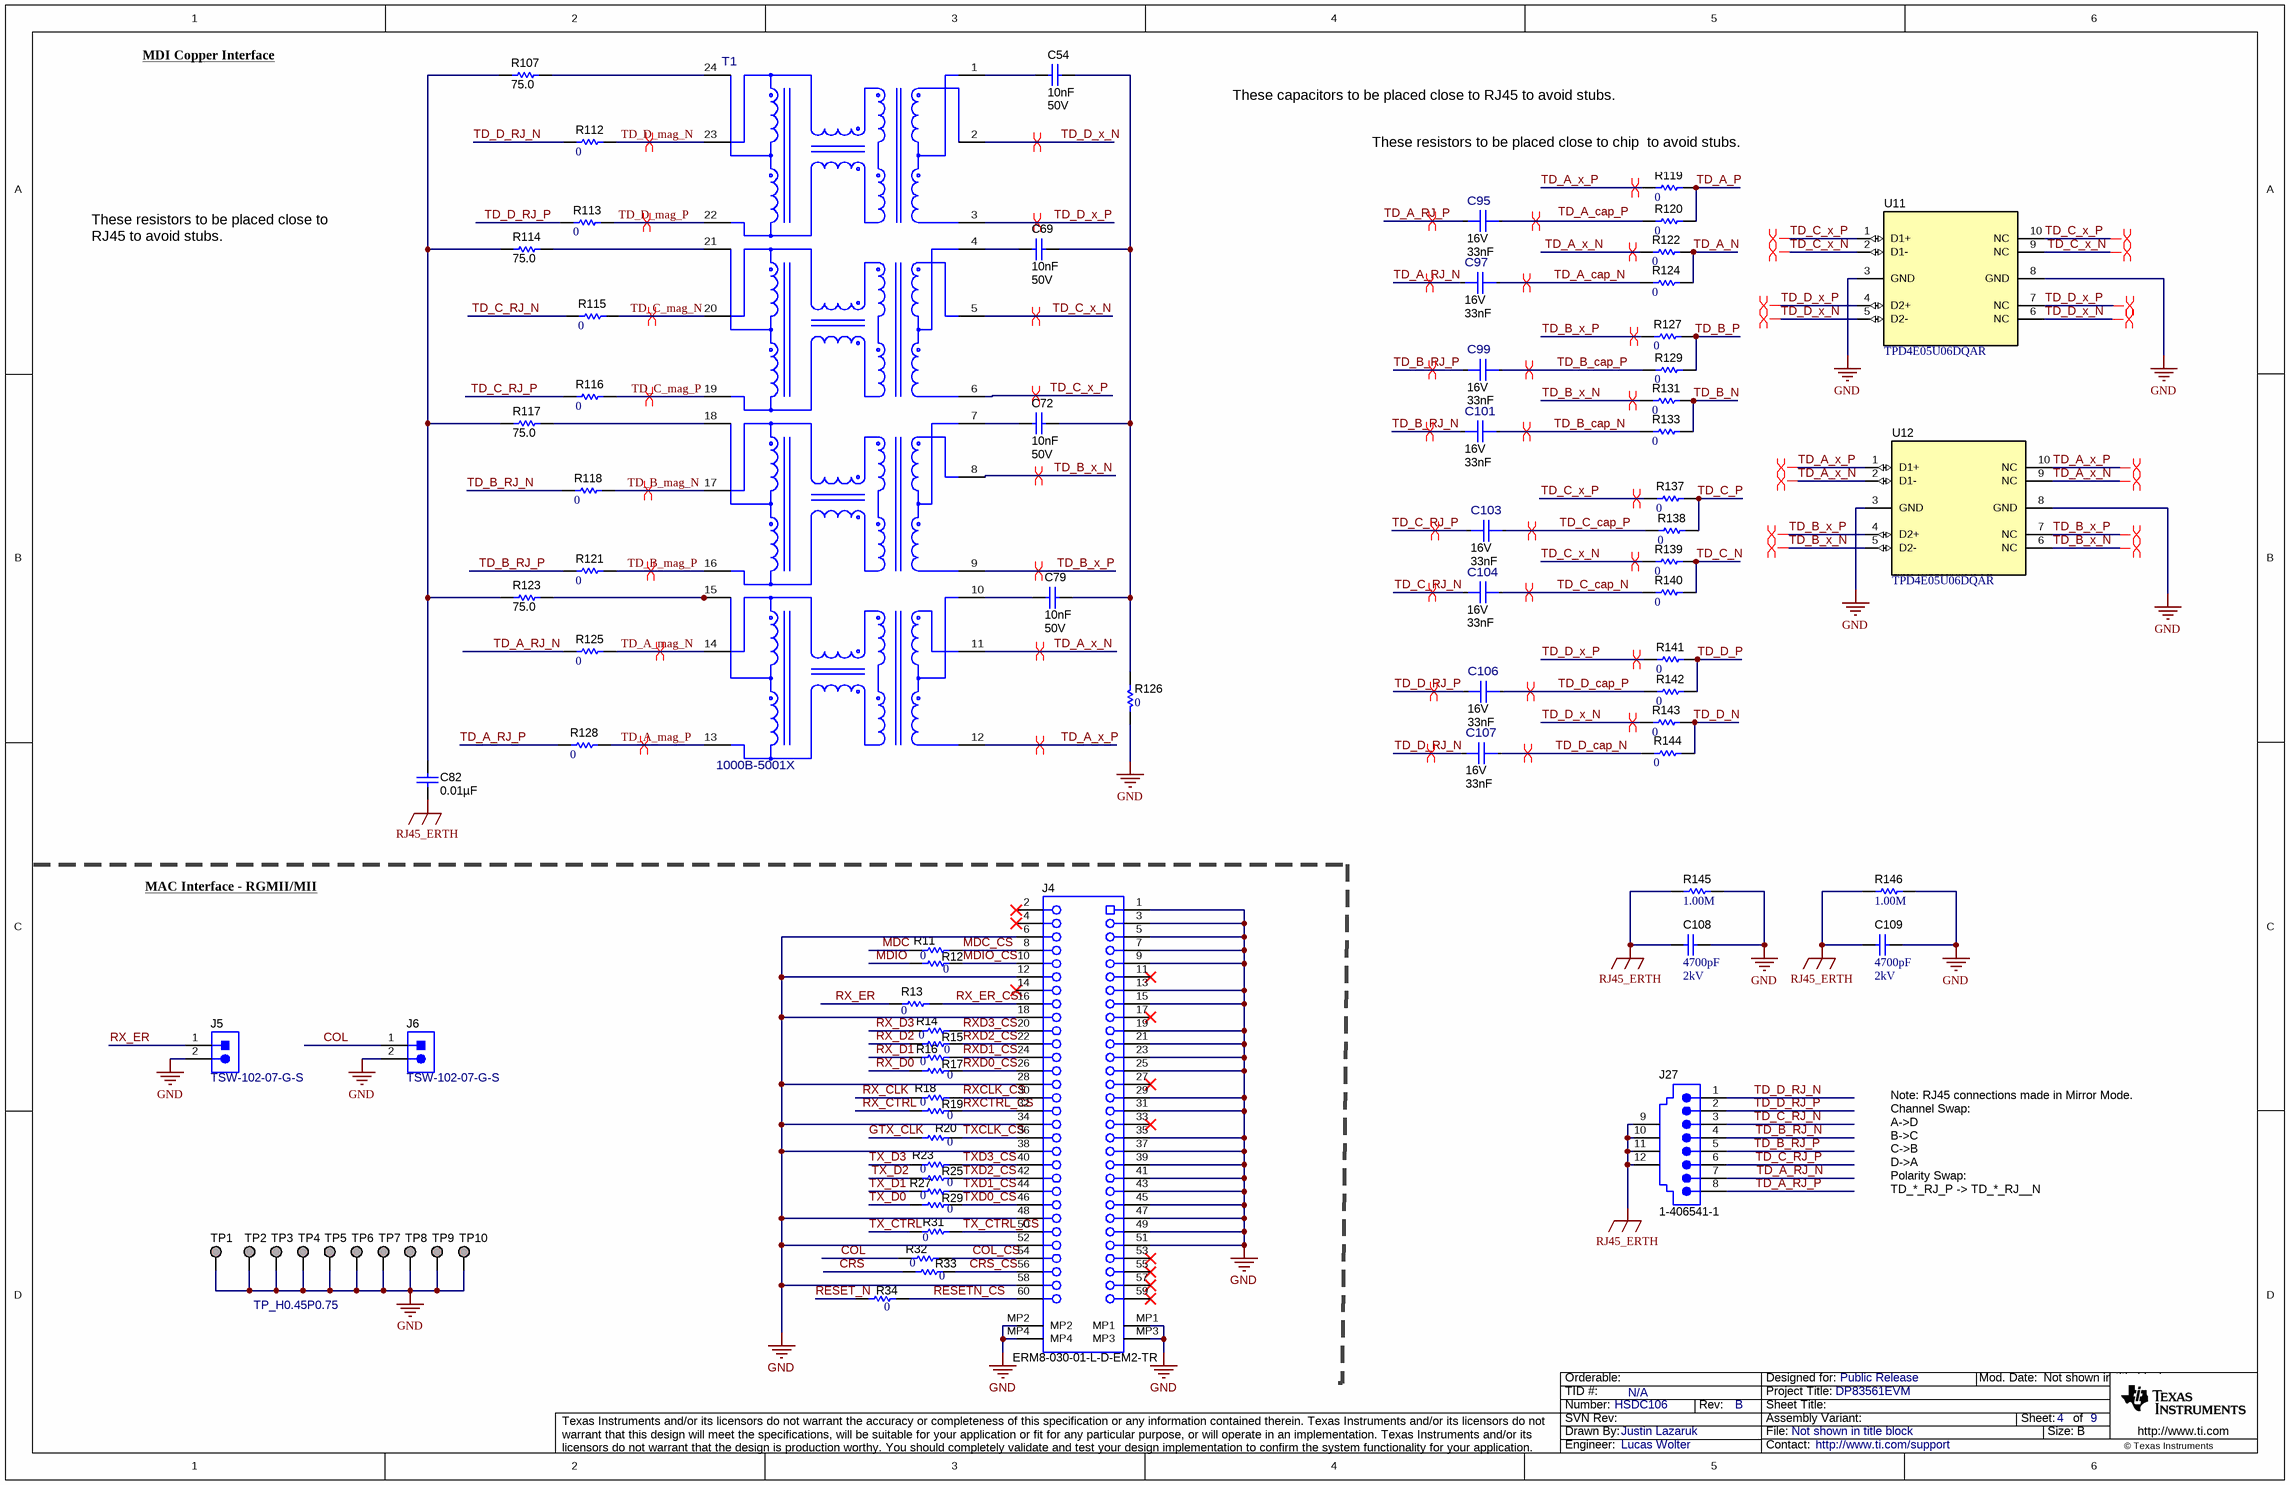
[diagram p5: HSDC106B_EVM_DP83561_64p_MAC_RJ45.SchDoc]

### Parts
C54  Cap_F: 10nF  VDC_V: 50V  [0603]  (hidden comment: CMP-0006850-4)
C69  Cap_F: 10nF  VDC_V: 50V  [0603]  (hidden comment: CMP-0006850-4)
C72  Cap_F: 10nF  VDC_V: 50V  [0603]  (hidden comment: CMP-0006850-4)
C79  Cap_F: 10nF  VDC_V: 50V  [0603]  (hidden comment: CMP-0006850-4)
C82  ValueDisplayed: 0.01µF  [0402]  (hidden comment: C0402C103J5RACTU)
C95  VDC_V: 16V  ValueDisplayed: 33nF  [FP-CGA2B2X5R1C333K050BA_0402-MFG]  (hidden comment: CGA2B2X5R1C333K050BA)
C97  VDC_V: 16V  ValueDisplayed: 33nF  [FP-CGA2B2X5R1C333K050BA_0402-MFG]  (hidden comment: CGA2B2X5R1C333K050BA)
C99  VDC_V: 16V  ValueDisplayed: 33nF  [FP-CGA2B2X5R1C333K050BA_0402-MFG]  (hidden comment: CGA2B2X5R1C333K050BA)
C101  VDC_V: 16V  ValueDisplayed: 33nF  [FP-CGA2B2X5R1C333K050BA_0402-MFG]  (hidden comment: CGA2B2X5R1C333K050BA)
C103  VDC_V: 16V  ValueDisplayed: 33nF  [FP-CGA2B2X5R1C333K050BA_0402-MFG]  (hidden comment: CGA2B2X5R1C333K050BA)
C104  VDC_V: 16V  ValueDisplayed: 33nF  [FP-CGA2B2X5R1C333K050BA_0402-MFG]  (hidden comment: CGA2B2X5R1C333K050BA)
C106  VDC_V: 16V  ValueDisplayed: 33nF  [FP-CGA2B2X5R1C333K050BA_0402-MFG]  (hidden comment: CGA2B2X5R1C333K050BA)
C107  VDC_V: 16V  ValueDisplayed: 33nF  [FP-CGA2B2X5R1C333K050BA_0402-MFG]  (hidden comment: CGA2B2X5R1C333K050BA)
C108  ValueDisplayed: 4700pF  VDC_V: 2kV  [1812_254]  (hidden comment: CMP-0009295-2)
C109  ValueDisplayed: 4700pF  VDC_V: 2kV  [1812_254]  (hidden comment: CMP-0009295-2)
J4  ERM8-030-01-L-D-EM2-TR  [Samtec_ERM8-030-01-L-D-EM2]
J5  TSW-102-07-G-S  [TSW-102-07-G-S]
J6  TSW-102-07-G-S  [TSW-102-07-G-S]
J27  1-406541-1  [TEC_1-406541-1]
R11  ValueDisplayed: 0  [0402]  (hidden comment: ERJ-2GE0R00X)
R12  ValueDisplayed: 0  [0402]  (hidden comment: ERJ-2GE0R00X)
R13  ValueDisplayed: 0  [0402]  (hidden comment: ERJ-2GE0R00X)
R14  ValueDisplayed: 0  [0402]  (hidden comment: ERJ-2GE0R00X)
R15  ValueDisplayed: 0  [0402]  (hidden comment: ERJ-2GE0R00X)
R16  ValueDisplayed: 0  [0402]  (hidden comment: ERJ-2GE0R00X)
R17  ValueDisplayed: 0  [0402]  (hidden comment: ERJ-2GE0R00X)
R18  ValueDisplayed: 0  [0402]  (hidden comment: ERJ-2GE0R00X)
R19  ValueDisplayed: 0  [0402]  (hidden comment: ERJ-2GE0R00X)
R20  ValueDisplayed: 0  [0402]  (hidden comment: ERJ-2GE0R00X)
R23  ValueDisplayed: 0  [0402]  (hidden comment: ERJ-2GE0R00X)
R25  ValueDisplayed: 0  [0402]  (hidden comment: ERJ-2GE0R00X)
R27  ValueDisplayed: 0  [0402]  (hidden comment: ERJ-2GE0R00X)
R29  ValueDisplayed: 0  [0402]  (hidden comment: ERJ-2GE0R00X)
R31  ValueDisplayed: 0  [0402]  (hidden comment: ERJ-2GE0R00X)
R32  ValueDisplayed: 0  [0402]  (hidden comment: ERJ-2GE0R00X)
R33  ValueDisplayed: 0  [0402]  (hidden comment: ERJ-2GE0R00X)
R34  ValueDisplayed: 0  [0402]  (hidden comment: ERJ-2GE0R00X)
R107  ValueDisplayed: 75.0  [0402]  (hidden comment: CMP-0026544-2)
R112  ValueDisplayed: 0  [0402]  (hidden comment: ERJ-2GE0R00X)
R113  ValueDisplayed: 0  [0402]  (hidden comment: ERJ-2GE0R00X)
R114  ValueDisplayed: 75.0  [0402]  (hidden comment: CMP-0026544-2)
R115  ValueDisplayed: 0  [0402]  (hidden comment: ERJ-2GE0R00X)
R116  ValueDisplayed: 0  [0402]  (hidden comment: ERJ-2GE0R00X)
R117  ValueDisplayed: 75.0  [0402]  (hidden comment: CMP-0026544-2)
R118  ValueDisplayed: 0  [0402]  (hidden comment: ERJ-2GE0R00X)
R119  ValueDisplayed: 0  [0402]  (hidden comment: ERJ-2GE0R00X)
R120  ValueDisplayed: 0  [0402]  (hidden comment: ERJ-2GE0R00X)
R121  ValueDisplayed: 0  [0402]  (hidden comment: ERJ-2GE0R00X)
R122  ValueDisplayed: 0  [0402]  (hidden comment: ERJ-2GE0R00X)
R123  ValueDisplayed: 75.0  [0402]  (hidden comment: CMP-0026544-2)
R124  ValueDisplayed: 0  [0402]  (hidden comment: ERJ-2GE0R00X)
R125  ValueDisplayed: 0  [0402]  (hidden comment: ERJ-2GE0R00X)
R126  ValueDisplayed: 0  [0402]  (hidden comment: ERJ-2GE0R00X)
R127  ValueDisplayed: 0  [0402]  (hidden comment: ERJ-2GE0R00X)
R128  ValueDisplayed: 0  [0402]  (hidden comment: ERJ-2GE0R00X)
R129  ValueDisplayed: 0  [0402]  (hidden comment: ERJ-2GE0R00X)
R131  ValueDisplayed: 0  [0402]  (hidden comment: ERJ-2GE0R00X)
R133  ValueDisplayed: 0  [0402]  (hidden comment: ERJ-2GE0R00X)
R137  ValueDisplayed: 0  [0402]  (hidden comment: ERJ-2GE0R00X)
R138  ValueDisplayed: 0  [0402]  (hidden comment: ERJ-2GE0R00X)
R139  ValueDisplayed: 0  [0402]  (hidden comment: ERJ-2GE0R00X)
R140  ValueDisplayed: 0  [0402]  (hidden comment: ERJ-2GE0R00X)
R141  ValueDisplayed: 0  [0402]  (hidden comment: ERJ-2GE0R00X)
R142  ValueDisplayed: 0  [0402]  (hidden comment: ERJ-2GE0R00X)
R143  ValueDisplayed: 0  [0402]  (hidden comment: ERJ-2GE0R00X)
R144  ValueDisplayed: 0  [0402]  (hidden comment: ERJ-2GE0R00X)
R145  ValueDisplayed: 1.00M  [0402]  (hidden comment: CMP-0026727-1)
R146  ValueDisplayed: 1.00M  [0402]  (hidden comment: CMP-0026727-1)
T1  1000B-5001X  [FP-1000B-5001X_SMD24-MFG]
TP1  TP_H0.45P0.75  [TP_H045P075]  (no BOM)
TP2  (no value)  [TP_H045P075]  (no BOM)
TP3  (no value)  [TP_H045P075]  (no BOM)
TP4  (no value)  [TP_H045P075]  (no BOM)
TP5  (no value)  [TP_H045P075]  (no BOM)
TP6  (no value)  [TP_H045P075]  (no BOM)
TP7  (no value)  [TP_H045P075]  (no BOM)
TP8  (no value)  [TP_H045P075]  (no BOM)
TP9  (no value)  [TP_H045P075]  (no BOM)
TP10  (no value)  [TP_H045P075]  (no BOM)
U11  TPD4E05U06DQAR  [DQA0010A]
U12  TPD4E05U06DQAR  [DQA0010A]

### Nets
GND: C108.1 C109.1 J4.1 J4.3 J4.5 J4.6 J4.7 J4.9 J4.12 J4.13 J4.15 J4.18 J4.19 J4.21 J4.23 J4.25 J4.28 J4.29 J4.31 J4.34 J4.35 J4.37 J4.38 J4.39 J4.41 J4.43 J4.45 J4.47 J4.48 J4.49 J4.51 J4.52 J4.58 J4.MP1 J4.MP2 J4.MP3 J4.MP4 J5.2 J6.2 R126.1 R145.2 R146.2 TP1.1 TP2.1 TP3.1 TP4.1 TP5.1 TP6.1 TP7.1 TP8.1 TP9.1 TP10.1 U11.3(GND) U11.8(GND) U12.3(GND) U12.8(GND)
RJ45_ERTH: C82.2 C108.2 C109.2 J27.9 J27.10 J27.11 J27.12 R145.1 R146.1
COL: J6.1 R32.1
COL_CS: J4.54 R32.2
CRS: R33.1
CRS_CS: J4.56 R33.2
GTX_CLK: R20.1
MDC: R11.1
MDC_CS: J4.8 R11.2
MDIO: R12.1
MDIO_CS: J4.10 R12.2
RESET_N: R34.1
RESETN_CS: J4.60 R34.2
RX_CLK: R18.1
RX_CTRL: R19.1
RX_D0: R17.1
RX_D1: R16.1
RX_D2: R15.1
RX_D3: R14.1
RX_ER: J5.1 R13.1
RX_ER_CS: J4.16 R13.2
RXCLK_CS: J4.30 R18.2
RXCTRL_CS: J4.32 R19.2
RXD0_CS: J4.26 R17.2
RXD1_CS: J4.24 R16.2
RXD2_CS: J4.22 R15.2
RXD3_CS: J4.20 R14.2
TD_A_cap_N: C97.1 R124.1
TD_A_mag_N: R125.2 T1.14(MX4+)
TD_A_mag_P: R128.2 T1.13(MX4-)
TD_A_N: R122.2 R124.2
TD_A_P: R119.2 R120.2
TD_A_RJ_N: C97.2 J27.7 R125.1
TD_A_RJ_P: C95.2 J27.8 R128.1
TD_A_x_N: R122.1 T1.11(TD4+) U12.2(D1-) U12.9(NC)
TD_A_x_P: R119.1 T1.12(TD4-) U12.1(D1+) U12.10(NC)
TD_B_cap_N: C101.1 R133.1
TD_B_cap_P: C99.1 R129.1
TD_B_mag_N: R118.2 T1.17(MX3+)
TD_B_mag_P: R121.2 T1.16(MX3-)
TD_B_N: R131.2 R133.2
TD_B_P: R127.2 R129.2
TD_B_RJ_N: C101.2 J27.4 R118.1
TD_B_RJ_P: C99.2 J27.5 R121.1
TD_B_x_N: R131.1 T1.8(TD3+) U12.5(D2-) U12.6(NC)
TD_B_x_P: R127.1 T1.9(TD3-) U12.4(D2+) U12.7(NC)
TD_C_cap_N: C104.1 R140.1
TD_C_cap_P: C103.1 R138.1
TD_C_mag_N: R115.2 T1.20(MX2+)
TD_C_mag_P: R116.2 T1.19(MX2-)
TD_C_N: R139.2 R140.2
TD_C_P: R137.2 R138.2
TD_C_RJ_N: C104.2 J27.3 R115.1
TD_C_RJ_P: C103.2 J27.6 R116.1
TD_C_x_N: R139.1 T1.5(TD2+) U11.2(D1-) U11.9(NC)
TD_C_x_P: R137.1 T1.6(TD2-) U11.1(D1+) U11.10(NC)
TD_D_cap_N: C107.1 R144.1
TD_D_cap_P: C106.1 R142.1
TD_D_mag_N: R112.2 T1.23(MX1+)
TD_D_mag_P: R113.2 T1.22(MX1-)
TD_D_N: R143.2 R144.2
TD_D_P: R141.2 R142.2
TD_D_RJ_N: C107.2 J27.1 R112.1
TD_D_RJ_P: C106.2 J27.2 R113.1
TD_D_x_N: R143.1 T1.2(TD1+) U11.5(D2-) U11.6(NC)
TD_D_x_P: R141.1 T1.3(TD1-) U11.4(D2+) U11.7(NC)
TX_CTRL: R31.1
TX_CTRL_CS: J4.50 R31.2
TX_D0: R29.1
TX_D1: R27.1
TX_D2: R25.1
TX_D3: R23.1
TXCLK_CS: J4.36 R20.2
TXD0_CS: J4.46 R29.2
TXD1_CS: J4.44 R27.2
TXD2_CS: J4.42 R25.2
TXD3_CS: J4.40 R23.2
NetC54_1: C54.1 C69.1 C72.1 C79.1 R126.2
NetC54_2: C54.2 T1.1(TCT1)
NetC69_2: C69.2 T1.4(TCT2)
NetC72_2: C72.2 T1.7(TCT3)
NetC79_2: C79.2 T1.10(TCT4)
NetC82_1: C82.1 R107.1 R114.1 R117.1 R123.1
NetC95_1: C95.1 R120.1
NetR107_2: R107.2 T1.24(MCT1)
NetR114_2: R114.2 T1.21(MCT2)
NetR117_2: R117.2 T1.18(MCT3)
NetR123_2: R123.2 T1.15(MCT4)

Not connected (* = marked no-connect by the designer): J4 2* 4* 11* 14* 17* 27* 33* 53* 55* 57* 59*

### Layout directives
differential pair: NetC95_1, TD_A_cap_N, TD_A_mag_N, TD_A_mag_P, TD_A_RJ_N, TD_A_RJ_P, TD_A_x_N, TD_A_x_P, TD_B_cap_N, TD_B_cap_P, TD_B_mag_N, TD_B_mag_P, TD_B_RJ_N, TD_B_RJ_P, TD_B_x_N, TD_B_x_P, TD_C_cap_N, TD_C_cap_P, TD_C_mag_N, TD_C_mag_P, TD_C_RJ_N, TD_C_RJ_P, TD_C_x_N, TD_C_x_P, TD_D_cap_N, TD_D_cap_P, TD_D_mag_N, TD_D_mag_P, TD_D_RJ_N, TD_D_RJ_P, TD_D_x_N, TD_D_x_P

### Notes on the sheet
- MDI Copper Interface
- These capacitors to be placed close to RJ45 to avoid stubs.
- (near R119) These resistors to be placed close to chip  to avoid stubs.
- These resistors to be placed close to RJ45 to avoid stubs.
- MAC Interface - RGMII/MII
- Note: RJ45 connections made in Mirror Mode.
  Channel Swap:
  A->D
  B->C
  C->B
  D->A
  Polarity Swap:
  TD_*_RJ_P -> TD_*_RJ__N
- Labels drawn without touching a wire or pin: TD_A_cap_P

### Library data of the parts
C54 C69 C72 C79 = CMP-0006850-4: CAP, CERM, 0.01 uF, 50 V, +/- 5%, X7R, 0603; PartNumber: C0603C103J5RACTU; Manufacturer: Kemet; Polarized: N; Value: 0.01uF; U/M: EA; Value1: Unknown; TaMin_C: -55°C; TaMax_C: 125°C; SizeAreaWB_mm2: 4.68; SizeZ_mm: 1; SizeX_mm: 1.6; SizeY_mm: 0.8; SizeArea_mm2: 1.28; AEC Category: Q200
C82 = CMP-0006236-2: CAP, CERM, 0.01 µF, 50 V, +/- 5%, X7R, 0402; Manufacturer: Kemet; Polarized: N; CompType: Capacitor; Value: 0.01uF; U/M: EA; Cap_F: 0.00000001; Tolerance_%: 5; Value1: Unknown; VDC_V: 50; Value2: 50V; TaMin_C: -55; TaMax_C: 125
C95 C97 C99 C101 C103 C104 C106 C107 = CMP-0091134-2: Cap Ceramic 33nF 16V X5R 10% Pad SMD 0402 +85°C Automotive T/R; Manufacturer: TDK Corporation; SizeZ_mm: 0.55mm; AEC Grade: Grade 3; TempCo: 15%; AEC Qualified: Yes
C108 C109 = CMP-0009295-2: CAP, CERM, 4700 pF, 2000 V, +/- 10%, X7R, 1812; PartNumber: 1812GC472KAT1A; Manufacturer: AVX; Polarized: N; Value: 4700pF; U/M: EA; Cap_F: 4.7nF; Value1: Unknown; Value2: 2000V; TaMin_C: -55°C; TaMax_C: 125°C; Cap_Case: 1812; SizeAreaWB_mm2: 23.1; SizeZ_mm: 2.54; SizeX_mm: 4.5; SizeY_mm: 3.2; SizeArea_mm2: 14.4; AEC Category: Q200
J4 = CMP-0055619-1: Receptacle, 0.8mm, 30x2, Tin, Edge mount; Manufacturer: Samtec; CNHeader: FALSE; Current_A: 2.2A; Gender: Female; Voltage_V: 200V; Row_Count: 2; Pitch_mm: 0.8; Cert_UL: Y
J5 J6 = CMP-0075405-3: as J10 on sheet HSDC106B_EVM_DP83561_64p_PHY
J27 = CMP-0054918-1: RJ-45, Right Angle, No LED, tab up; Manufacturer: AMP; SymbolCreator: x0208326; CompType: Connector; U/M: EA; Note: updated F/S per request.  Made footprint to max size.  2103-11-27
R11-R20 R23 R25 R27 R29 R31-R34 R112 R113 R115 R116 R118-R122 R124-R129 R131 R133 R137-R144 = CMP-0026992-3: as R58 on sheet HSDC106B_EVM_DP83561_64p_MSP430
R107 R114 R117 R123 = CMP-0026544-2: RES, 75.0, 1%, 0.063 W, AEC-Q200 Grade 0, 0402; PartNumber: CRCW040275R0FKED; Manufacturer: Vishay-Dale; Value: 75.0; Res_ohm: 75; Value_Code: 75R0; Power_W: 63mW; Value2: 0.063W; VDC_V: 50V; TempCo: 100 ppm/C; EIA_Code: E96; SizeX_mm: 1; SizeY_mm: 0.5; SizeZ_mm: 0.6; AEC Qualified: Y; AEC Category: Q200; AEC Grade: 0
R145 R146 = CMP-0026727-1: as R81 on sheet HSDC106B_EVM_DP83561_64p_PHY
T1 = CMP-0090858-1: 350µH LAN 10/100/1000 Base-T Pulse Transformer 1:1 Surface Mount; Manufacturer: Pulse Electronics; AEC Qualified: No; SizeZ_mm: 5.97mm; Return Loss: -8dB; Insertion Loss: -1.4dB; Standoff Height: 0mm; Voltage_Isolation_Vrms: 1500Vrms
TP1 = CMP-0003719-1: as VPP_TP1 on sheet HSDC106B_EVM_DP83561_64p_PHY
TP2-TP10 = CMP-0003719-1: Testpoint; Manufacturer: Texas Instruments; Key: TP_H0.45P0.75; CompType: Pad
U11 U12 = CMP-0073613-3: 4-Channel Ultra-Low-Capacitance IEC ESD Protection Diode, DQA0010A (USON-10); Manufacturer: Texas Instruments; CompType: IC; Green_Lifecycle: Active; SizeAreaWB_mm2: 7.0; Green_REACh: Passed; SizeZ_mm: 0.55; SizeX_mm: 1.0; SizeY_mm: 2.5; AEC Category: Q200; AEC Qualified: N

## Sheet HSDC106B_EVM_DP83561_64p_Hardware.SchDoc
size 431 x 279 mm; Date: Not shown in title block; ApprovedBy: Not shown in title block; CheckedBy: Not shown in title block; Author: Not shown in title block; CompanyName: Not shown in title block; Engineer: Not shown in title block; Organization: Not shown in title block; Address1: Not shown in title block; Address2: Not shown in title block; Address3: Not shown in title block; Address4: Not shown in title block; DocumentNumber: 9; Revision: Use project parameter SCH_Rev; SheetNumber: 9; SheetTotal: 9; PageSetup: Record=PageOptions¦CenterHorizontal=True¦CenterVertical=True¦PrintScale=1.00¦XCorrection=1.00¦YCorrection=1.00¦PrintKind=0¦BorderSize=5000000¦LeftOffset=0¦BottomOffset=0¦Orientation=2¦PaperLength=1000¦PaperWidth=1000¦Scale=100¦PaperSource=15¦PrintQuality=600¦MediaType=1¦DitherType=10¦PaperKind=Letter¦PrintScaleMode=1
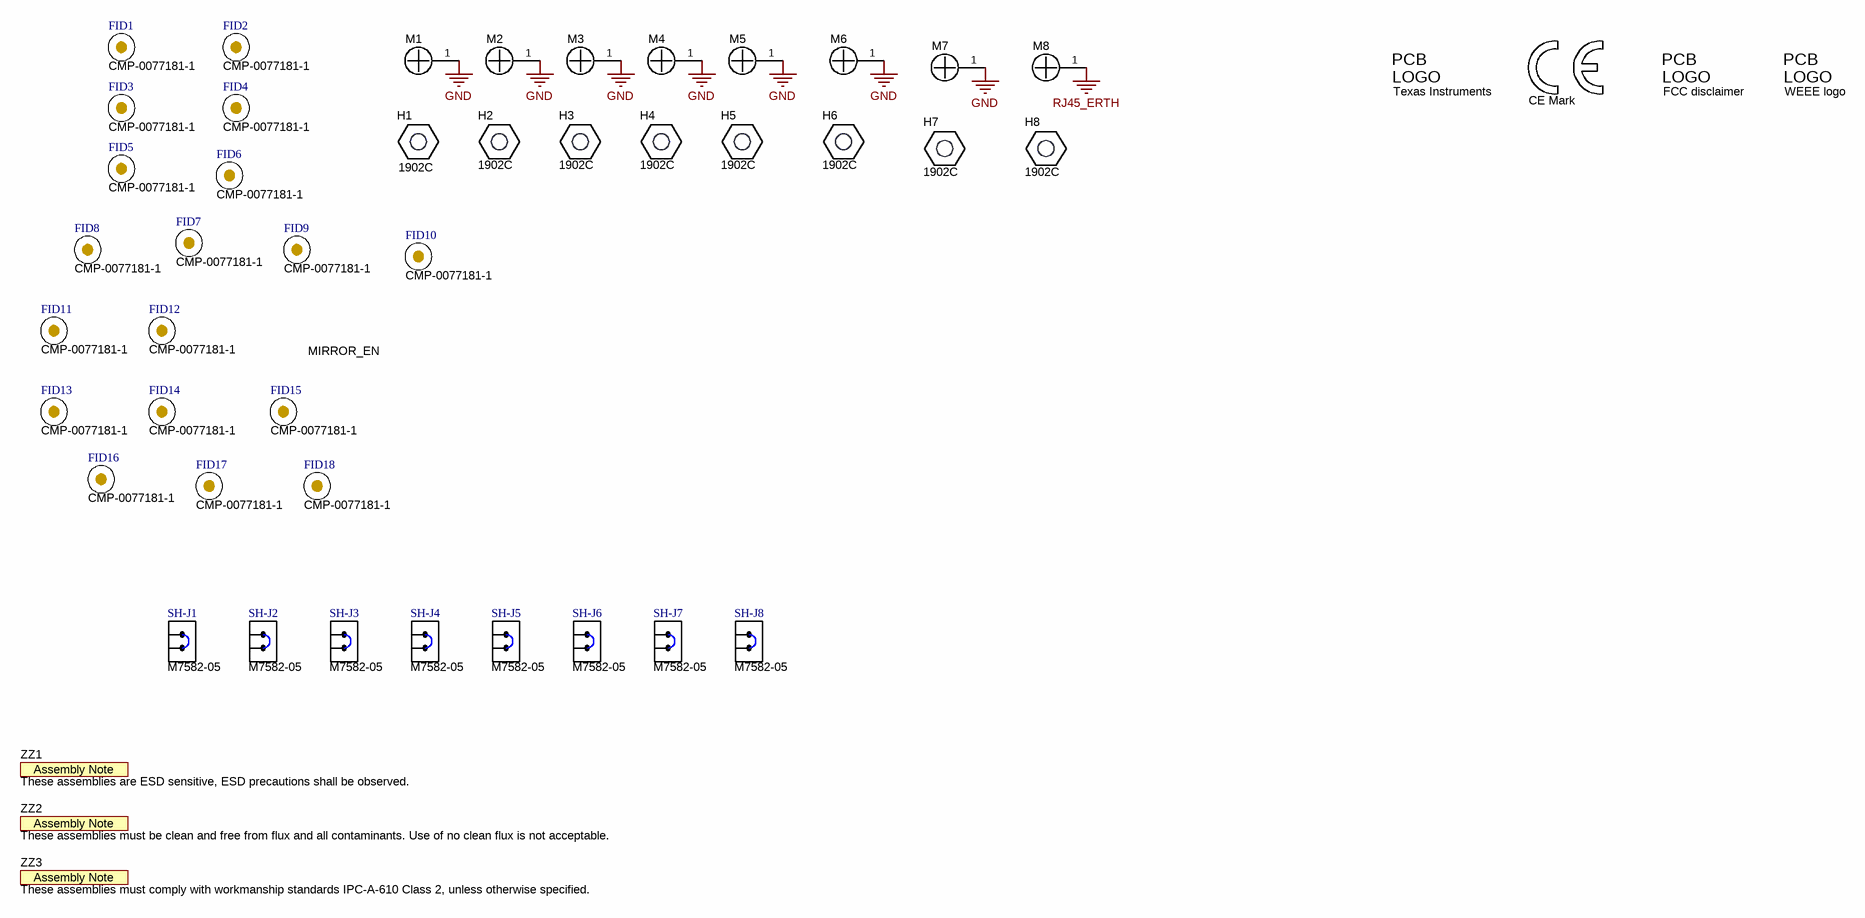
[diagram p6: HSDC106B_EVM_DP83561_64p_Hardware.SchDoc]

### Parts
FID1  CMP-0077181-1  [Fiducial10-30]
FID2  CMP-0077181-1  [Fiducial10-30]
FID3  CMP-0077181-1  [Fiducial10-30]
FID4  CMP-0077181-1  [Fiducial10-30]
FID5  CMP-0077181-1  [Fiducial10-30]
FID6  CMP-0077181-1  [Fiducial10-30]
FID7  CMP-0077181-1  [Fiducial10-30]
FID8  CMP-0077181-1  [Fiducial10-30]
FID9  CMP-0077181-1  [Fiducial10-30]
FID10  CMP-0077181-1  [Fiducial10-30]
FID11  CMP-0077181-1  [Fiducial10-30]
FID12  CMP-0077181-1  [Fiducial10-30]
FID13  CMP-0077181-1  [Fiducial10-30]
FID14  CMP-0077181-1  [Fiducial10-30]
FID15  CMP-0077181-1  [Fiducial10-30]
FID16  CMP-0077181-1  [Fiducial10-30]
FID17  CMP-0077181-1  [Fiducial10-30]
FID18  CMP-0077181-1  [Fiducial10-30]
H1  1902C  [Keystone_1902C]
H2  1902C  [Keystone_1902C]
H3  1902C  [Keystone_1902C]
H4  1902C  [Keystone_1902C]
H5  1902C  [Keystone_1902C]
H6  1902C  [Keystone_1902C]
H7  1902C  [Keystone_1902C]
H8  1902C  [Keystone_1902C]
Logo1  CE Mark  [CE_Mark_5mm]  (no BOM)
Logo2  Texas Instruments  [TI_Stacked_Overlay_Small]  (no BOM)
Logo3  FCC disclaimer  [FCC_disclaimer]  (no BOM)
Logo4  WEEE logo  [WEEE_Minimum]  (no BOM)
M1  NY PMS 440 0025 PH  [NY PMS 440 0025 PH]  (value not drawn)
M2  NY PMS 440 0025 PH  [NY PMS 440 0025 PH]  (value not drawn)
M3  NY PMS 440 0025 PH  [NY PMS 440 0025 PH]  (value not drawn)
M4  NY PMS 440 0025 PH  [NY PMS 440 0025 PH]  (value not drawn)
M5  NY PMS 440 0025 PH  [NY PMS 440 0025 PH]  (value not drawn)
M6  NY PMS 440 0025 PH  [NY PMS 440 0025 PH]  (value not drawn)
M7  NY PMS 440 0025 PH  [NY PMS 440 0025 PH]  (value not drawn)
M8  NY PMS 440 0025 PH  [NY PMS 440 0025 PH]  (value not drawn)
SH-J1  M7582-05  [Harwin_M7582-05]
SH-J2  M7582-05  [Harwin_M7582-05]
SH-J3  M7582-05  [Harwin_M7582-05]
SH-J4  M7582-05  [Harwin_M7582-05]
SH-J5  M7582-05  [Harwin_M7582-05]
SH-J6  M7582-05  [Harwin_M7582-05]
SH-J7  M7582-05  [Harwin_M7582-05]
SH-J8  M7582-05  [Harwin_M7582-05]
ZZ1  These assemblies are ESD sensitive, ESD precautions shall be observed.  [AssemblyNote]  (no BOM)
ZZ2  These assemblies must be clean and free from flux and all contaminants. Use of no clean flux is not acceptable.  [AssemblyNote]  (no BOM)
ZZ3  These assemblies must comply with workmanship standards IPC-A-610 Class 2, unless otherwise specified.  [AssemblyNote]  (no BOM)

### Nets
GND: M1.1 M2.1 M3.1 M4.1 M5.1 M6.1 M7.1
RJ45_ERTH: M8.1

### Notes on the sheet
- MIRROR_EN

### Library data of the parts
FID1-FID18 = CMP-0077181-1: Fiducial mark.  There is nothing to buy or mount.
H1-H8 = CMP-0003610-1: Standoff, Hex, 0.5"L #4-40 Nylon; Manufacturer: Keystone; CompType: Hardware
Logo1 = CMP-0074844-1: SymbolCreator: a0412235
Logo2 = CMP-0074838-1: Texas Instrument Corporate Signature; SymbolCreator: a0412235; Lib Reference: TI_Logo; Library Reference: Logo
Logo3 = CMP-0074847-1: FCC_disclaimer; Library Reference: Logo
Logo4 = CMP-0074769-1
M1-M8 = CMP-0003617-1: Machine Screw, Round, #4-40 x 1/4, Nylon, Philips panhead; Manufacturer: B&F Fastener Supply; CompType: Hardware
SH-J1-SH-J8 = CMP-0078738-1: Single Operation 2.54mm Pitch Open Top Jumper Socket; Manufacturer: Harwin
ZZ1 = CMP-0077236-1
ZZ2 = CMP-0077237-1
ZZ3 = CMP-0077238-1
